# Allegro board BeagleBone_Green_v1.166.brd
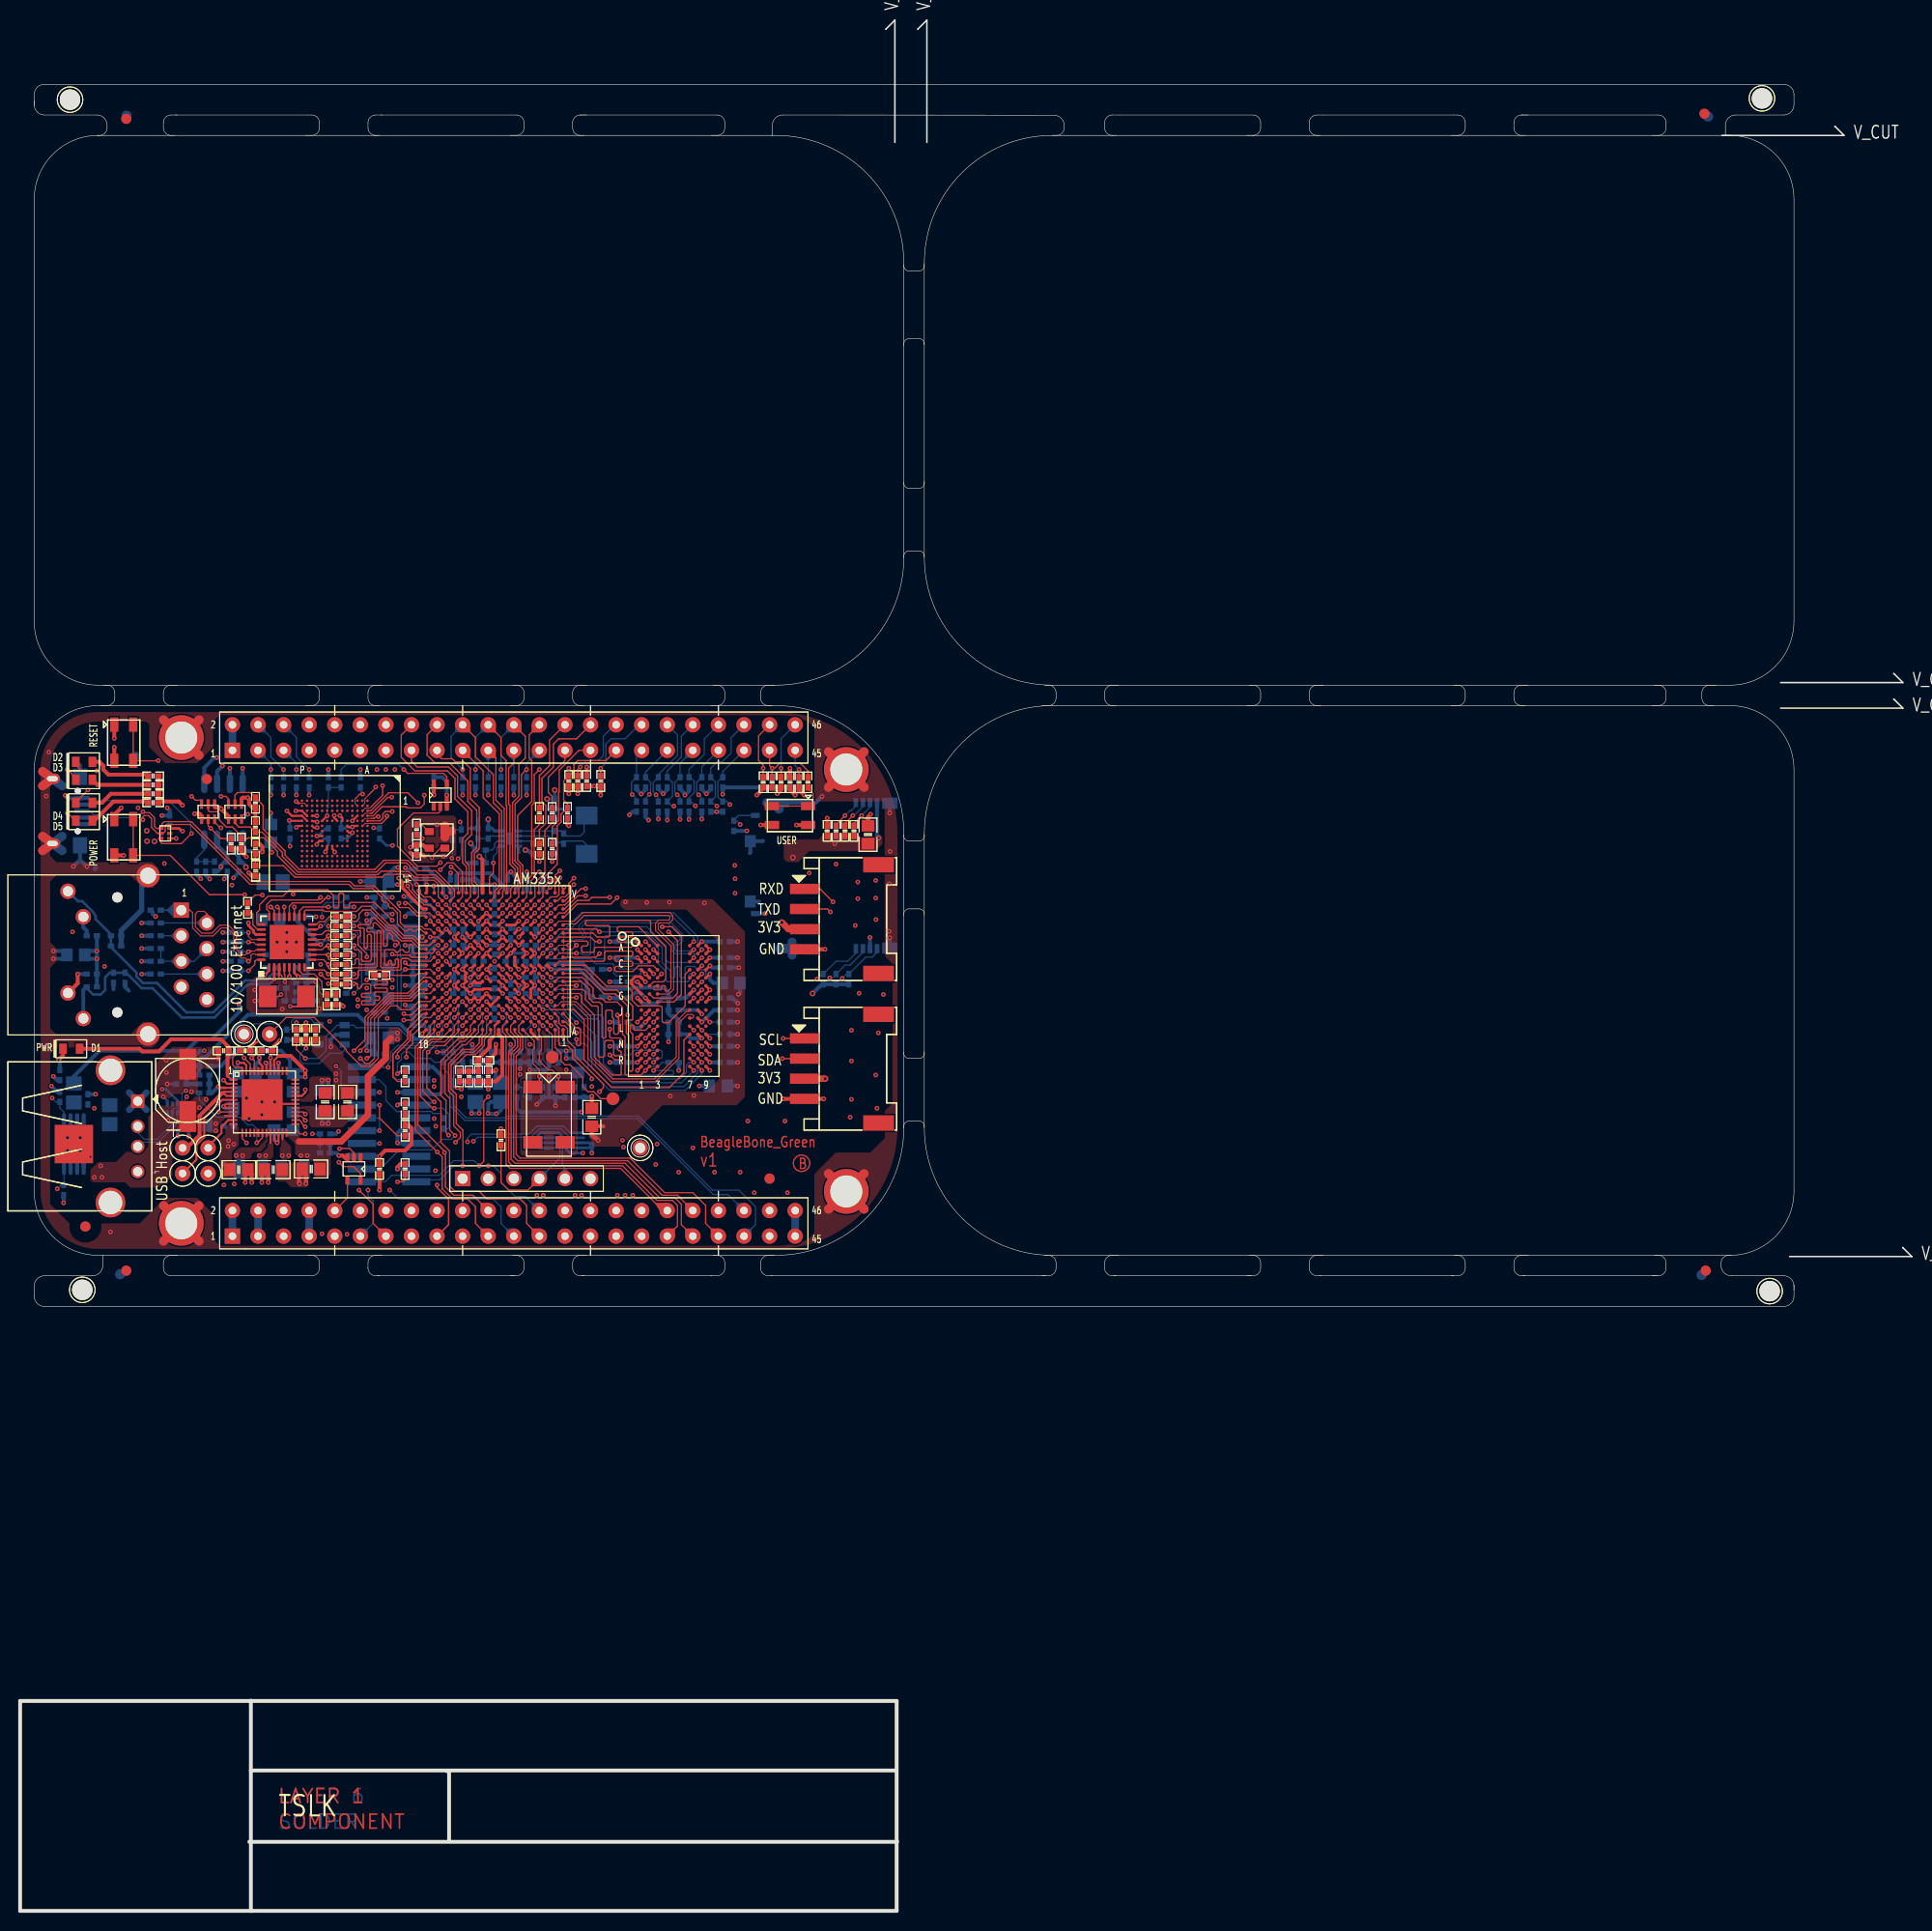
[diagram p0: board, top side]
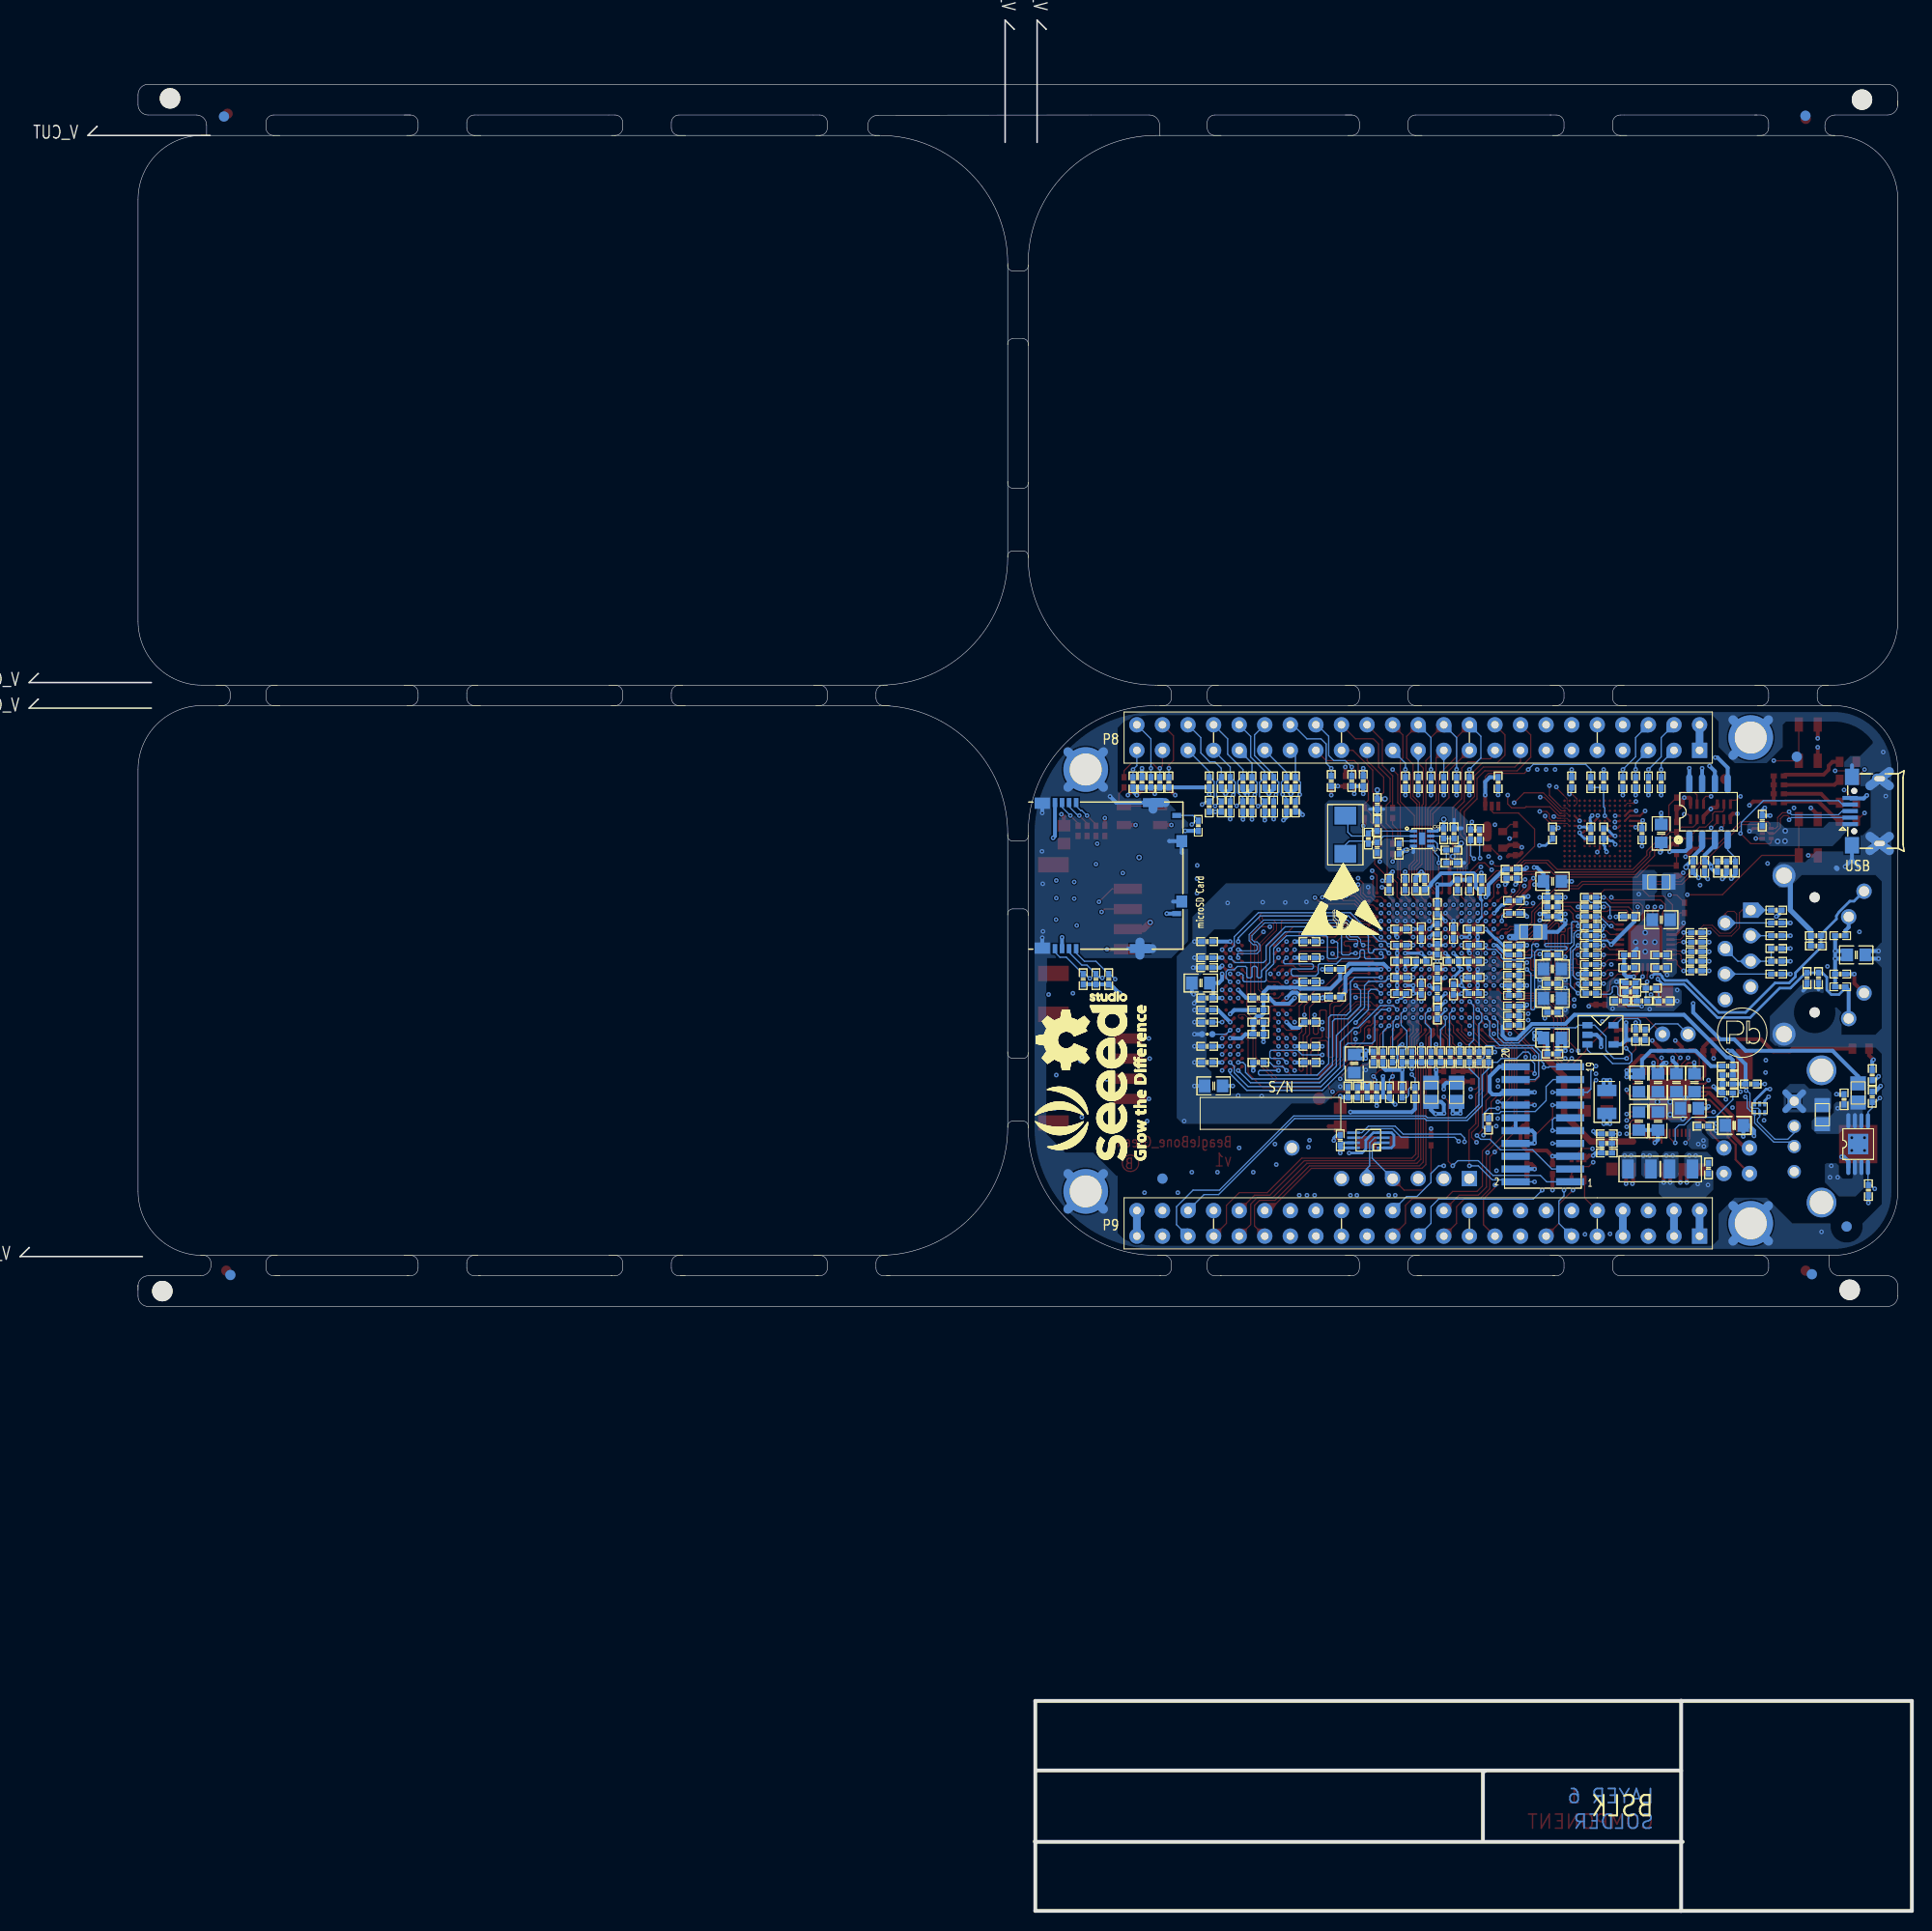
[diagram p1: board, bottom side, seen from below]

Outline 187.86 x 187.83 mm; copper layers: TOP, LYR2_GND, LYR3, LYR4, LYR5_PWR, BOTTOM. Coordinates in mm from the lower left corner of the outline.

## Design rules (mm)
net group RX: nets RXN RXP
net group TX: nets TXN TXP
net group USB0: nets USB0_DM USB0_DP
net group USB1: nets USB1_DM USB1_DP
net group CLK: nets MMC0_CLKO
net group DDR_ADD: nets DDR_A0 DDR_A1 DDR_A2 DDR_A3 DDR_A4 DDR_A5 DDR_A6 DDR_A7 DDR_A8 DDR_A9 DDR_A10 DDR_A11 DDR_A12 DDR_A13 DDR_A14 DDR_BA0 DDR_BA1 DDR_BA2 DDR_CASN DDR_CKE DDR_CLK DDR_CLKN DDR_CSN DDR_ODT DDR_RASN DDR_WEN
net group DDR_DQ0: nets DDR_D0 DDR_D1 DDR_D2 DDR_D3 DDR_D4 DDR_D5 DDR_D6 DDR_D7 DDR_DQM0 DDR_DQS0 DDR_DQSN0
net group DDR_DQ1: nets DDR_D8 DDR_D9 DDR_D10 DDR_D11 DDR_D12 DDR_D13 DDR_D14 DDR_D15 DDR_DQM1 DDR_DQS1 DDR_DQSN1
nets with their own width: min track width 0.203; nets USB1_VBUS

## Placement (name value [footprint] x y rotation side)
C1  10uF,10V  [805]  21.72 73.63 180 top
C2  10uF,10V  [805]  17.63 78.03 0 bottom
C3  0.1uf,6.3V  [402]  22.35 85.45 180 top
C4  10uF,10V  [805]  21.59 82.27 90 bottom
C7  10uF,10V  [805]  25.21 78.46 270 bottom
C8  10uF,10V  [805]  27.11 78.46 270 bottom
C9  10uF,10V  [805]  25.15 73.63 180 top
C10  10uF,10V  [805]  22.1 79.73 180 bottom
C11  10uF,10V  [805]  30.29 80.37 270 top
C12  10uF,10V  [805]  28.89 73.7 0 top
C13  10uF,10V  [805]  25.21 82.27 90 bottom
C14  10uF,10V  [805]  27.11 82.27 90 bottom
C15  10uF,10V  [805]  23.37 82.27 90 bottom
C16  2.2uF,6.3V  [402]  16 82.14 180 bottom
C17  2.2uF,6.3V  [402]  21.72 103.73 270 bottom
C18  2.2uF,6.3V  [402]  20.19 85.45 180 top
C19  470pF,6.3V  [402]  18.41 103.73 270 bottom
C20  0.1uf,6.3V  [402]  20.57 103.73 270 bottom
C21  18pF,50V  [402]  51.88 81.32 90 bottom
C22  18pF,50V  [402]  53.15 81.32 90 bottom
C24  2.2uF,6.3V  [402]  30.29 76.24 0 bottom
C25  18pF,50V  [402]  53.09 107.8 90 bottom
C26  18pF,50V  [402]  53.09 105.64 270 bottom
C28  0.1uf,6.3V  [402]  57.28 93.54 0 bottom
C29  0.1uf,6.3V  [402]  35.69 73.7 270 top
C30  0.1uf,6.3V  [402]  30.29 75.29 0 bottom
C31  0.1uf,6.3V  [402]  44.58 82.91 270 top
C32  0.001uf,50V  [402]  43.62 82.91 270 top
C33  0.1uf,6.3V  [402]  45.53 82.91 270 top
C34  100uF,6.3V  [RD205SMD_250D]  16.64 81.51 90 top
C35  0.1uf,6.3V  [402]  6.73 80.62 90 bottom
C36  0.1uf,6.3V  [402]  14.86 108.31 90 bottom
C37  0.1uf,6.3V  [402]  29.34 87.03 270 top
C38  0.1uf,6.3V  [402]  35.69 99.73 180 bottom
C39  10uF,10V  [805]  35.69 90.65 0 bottom
C40  10uF,10V  [805]  35.69 93.57 0 bottom
C41  0.1uf,6.3V  [402]  43.52 97.54 180 bottom
C42  0.1uf,6.3V  [402]  47.12 97.54 270 bottom
C43  0.1uf,6.3V  [402]  48.72 97.14 90 bottom
C44  0.1uf,6.3V  [402]  39.52 90.94 180 bottom
C45  0.1uf,6.3V  [402]  39.5 94.97 180 bottom
C46  0.1uf,6.3V  [402]  45.52 94.34 0 bottom
C47  0.1uf,6.3V  [402]  47.12 95.54 270 bottom
C48  0.1uf,6.3V  [402]  48.72 94.34 0 bottom
C49  0.1uf,6.3V  [402]  47.12 93.14 90 bottom
C50  0.1uf,6.3V  [402]  48.72 91.54 90 bottom
C51  0.1uf,6.3V  [402]  35.69 94.97 180 bottom
C52  0.1uf,6.3V  [402]  35.69 92.11 180 bottom
C53  0.1uf,6.3V  [402]  35.69 89.26 180 bottom
C54  0.1uf,6.3V  [402]  39.52 91.94 180 bottom
C55  10uF,10V  [805]  32.51 80.37 270 top
C56  0.1uf,6.3V  [402]  47.12 99.54 270 bottom
C57  0.1uf,6.3V  [402]  56.26 112.24 270 top
C58  0.1uf,6.3V  [402]  43.92 101.94 90 bottom
C59  0.1uf,6.3V  [402]  44.89 84.81 270 bottom
C60  0.1uf,6.3V  [402]  43.52 92.74 180 bottom
C61  0.1uf,6.3V  [402]  76.45 112.12 270 top
C62  10uF,10V  [805]  35.69 86.72 0 bottom
C63  0.1uf,6.3V  [402]  45.52 91.54 90 bottom
C64  0.1uf,6.3V  [402]  35.69 85.13 180 bottom
C65  0.1uf,6.3V  [402]  43.52 94.34 180 bottom
C66  0.1uf,6.3V  [402]  43.52 95.94 180 bottom
C67  0.1uf,6.3V  [402]  35.69 100.69 180 bottom
C68  0.1uf,6.3V  [402]  50.32 101.94 270 bottom
C69  0.1uf,6.3V  [402]  39.52 93.94 0 bottom
C70  0.1uf,6.3V  [402]  43.52 91.14 180 bottom
C71  0.1uf,6.3V  [402]  39.75 102.59 180 bottom
C72  0.1uf,6.3V  [402]  47.12 91.14 270 bottom
C73  0.1uf,6.3V  [402]  50.72 97.54 0 bottom
C74  0.1uf,6.3V  [402]  51.92 101.94 270 bottom
C75  0.1uf,6.3V  [402]  54.48 112.24 270 bottom
C76  0.1uf,6.3V  [402]  76.45 112.12 270 bottom
C77  10uF,10V  [805]  35.69 102.27 180 bottom
C78  0.1uf,6.3V  [402]  35.69 98.78 0 bottom
C79  0.1uf,6.3V  [402]  39.52 92.94 180 bottom
C80  0.1uf,6.3V  [402]  42.72 101.94 90 bottom
C81  0.1uf,6.3V  [402]  49.28 101.96 90 bottom
C82  0.1uf,6.3V  [402]  39.52 89.89 180 bottom
C83  0.1uf,6.3V  [402]  39.52 88.94 180 bottom
C84  0.1uf,6.3V  [402]  48.39 101.96 90 bottom
C85  0.1uf,6.3V  [402]  39.52 87.99 180 bottom
C86  0.1uf,6.3V  [402]  39.52 100.37 180 bottom
C87  0.1uf,6.3V  [402]  39.5 95.86 180 bottom
C88  0.1uf,6.3V  [402]  47.12 89.13 270 bottom
C89  1uF,10V  [402]  47.75 84.81 270 bottom
C90  1uF,10V  [402]  45.85 84.81 270 bottom
C91  1uF,10V  [402]  46.8 84.81 270 bottom
C92  0.1uf,6.3V  [402]  49.66 84.81 270 bottom
C93  0.1uf,6.3V  [402]  46.48 82.91 270 top
C94  0.1uf,6.3V  [402]  45.52 97.14 270 bottom
C95  10uF,10V  [805]  55.37 84.18 90 bottom
C96  10uF,10V  [805]  56.77 78.84 90 top
C97  0.1uf,6.3V  [402]  50.72 95.94 180 bottom
C98  0.1uf,6.3V  [402]  50.72 94.34 180 bottom
C99  0.1uf,6.3V  [402]  50.72 92.74 180 bottom
C100  0.1uf,6.3V  [402]  50.72 91.14 180 bottom
C101  0.1uf,6.3V  [402]  53.47 84.81 270 bottom
C102  0.1uf,6.3V  [402]  55.05 81.32 90 bottom
C103  0.1uf,6.3V  [402]  56.01 81.32 90 bottom
C104  1uF,10V  [402]  50.61 84.81 270 bottom
C105  0.1uf,6.3V  [402]  48.7 84.81 270 bottom
C106  1uF,10V  [402]  45.12 101.94 90 bottom
C107  0.1uf,6.3V  [402]  59.82 96.29 180 bottom
C108  0.1uf,6.3V  [402]  59.82 94.69 180 bottom
C109  0.1uf,6.3V  [402]  59.82 92.29 180 bottom
C110  0.1uf,6.3V  [402]  59.82 90.69 180 bottom
C111  0.1uf,6.3V  [402]  59.82 88.29 180 bottom
C112  0.1uf,6.3V  [402]  59.82 85.89 180 bottom
C113  0.1uf,6.3V  [402]  59.82 84.29 180 bottom
C114  0.1uf,6.3V  [402]  69.98 96.29 0 bottom
C115  0.1uf,6.3V  [402]  69.98 94.69 0 bottom
C116  0.1uf,6.3V  [402]  69.98 93.7 0 bottom
C117  0.1uf,6.3V  [402]  69.98 90.69 0 bottom
C118  10uF,10V  [805]  70.61 92.18 180 bottom
C119  0.1uf,6.3V  [402]  69.98 89.49 0 bottom
C120  0.1uf,6.3V  [402]  69.98 85.89 0 bottom
C121  0.1uf,6.3V  [402]  69.98 84.29 0 bottom
C122  10uF,10V  [805]  69.34 81.95 180 bottom
C123  0.001uf,50V  [402]  64.9 89.49 0 bottom
C124  0.1uf,6.3V  [402]  64.9 87.09 180 bottom
C125  2.2uF,6.3V  [402]  33.78 112.12 90 bottom
C126  10uF,10V  [805]  24.89 107.04 90 bottom
C127  0.1uf,6.3V  [402]  26.8 107.04 270 bottom
C128  0.1uf,6.3V  [402]  30.61 107.04 90 bottom
C129  0.1uf,6.3V  [402]  31.88 107.04 270 bottom
C130  0.1uf,6.3V  [402]  35.69 107.04 270 bottom
C131  0.1uf,6.3V  [402]  24.89 93.7 0 bottom
C132  0.1uf,6.3V  [402]  24.89 94.97 0 bottom
C133  10uF,10V  [805]  24.89 98.46 180 bottom
C134  1uF,10V  [402]  28.07 93.7 180 bottom
C135  0.1uf,6.3V  [402]  28.07 98.78 0 bottom
C136  470pF,6.3V  [0402]  28.07 94.97 180 bottom
C137  33pF,4 EMI  [402]  13.46 99.42 180 bottom
C138  33pF,4 EMI  [402]  13.46 98.15 180 bottom
C139  33pF,4 EMI  [402]  13.46 96.88 180 bottom
C140  33pF,4 EMI  [402]  13.46 93.07 180 bottom
C141  0.022uF,10V  [402]  13.46 95.61 180 bottom
C142  30pF,50V  [402]  24.64 90.4 180 bottom
C143  30pF,50V  [402]  28.96 90.4 0 bottom
C152  0.1uf,6.3V  [402]  27.43 87.03 90 bottom
C153  10uF,10V  [805]  84.2 106.91 90 top
C154  0.1uf,6.3V  [402]  80.14 107.29 90 top
C155  0.1uf,6.3V  [402]  56.77 76.56 270 bottom
C158  0.1uf,6.3V  [402]  41.08 112.12 90 bottom
C159  0.1uf,6.3V  [402]  39.37 105.38 270 top
C161  33pF,4 EMI  [402]  27.94 92.18 0 bottom
C162  33pF,4 EMI  [402]  30.48 90.53 90 top
C163  100pF,4 EMI  [402]  9.53 96.88 0 bottom
C164  100pF,4 EMI  [402]  10.41 92.68 270 bottom
C165  100nF,4 EMI  [402]  9.53 95.86 0 bottom
C166  100nF,4 EMI  [402]  9.27 92.68 270 bottom
D1  LTST-C191TBKT  [LED_0603]  5.08 85.65 0 top
D2  LTST-C191TBKT  [LED_0603]  6.35 114.15 0 top
D3  LTST-C191TBKT  [LED_0603]  6.35 112.37 0 top
D4  LTST-C191TBKT  [LED_0603]  6.35 110.08 0 top
D5  LTST-C191TBKT  [LED_0603]  6.35 108.31 0 top
FB1  150OHM800mA  [SM-7351-IND-0805]  37.85 97.26 0 bottom
FB2  150OHM800mA  [SM-7351-IND-0805]  47.75 81.32 270 bottom
FB3  150OHM800mA  [SM-7351-IND-0805]  45.21 81.32 270 bottom
FB4  150OHM800mA  [SM-7351-IND-0805]  25.12 102.21 180 bottom
FB7  150OHM800mA  [SM-7351-IND-0805]  8.89 79.1 90 bottom
FB8  0.1R,0805  [SM-7351-IND-0805]  5.33 81.25 270 bottom
J1  HEADER 6  [SIP6]  43.94 72.75 90 top
J4  GroveHDR  [4P-SMD-2_0-90D]  77.85 83.67 270 top
J5  GroveHDR  [4P-SMD-2_0-90D]  77.85 98.53 270 top
L1  LQM2HPN2R2MG0L  [2520]  22.92 73.7 180 bottom
L2  LQM2HPN2R2MG0L  [2520]  27.05 73.7 0 bottom
L3  LQM2HPN2R2MG0L  [2520]  30.29 80.37 270 bottom
MTG1  MHOLE  [MTGH200C125D_PL]  16 68.3 90 top
MTG2  MHOLE  [MTGH200C125D_PL]  82.04 71.48 90 top
MTG3  MHOLE  [MTGH200C125D_PL]  16 116.56 90 top
MTG4  MHOLE  [MTGH200C125D_PL]  82.04 113.39 90 top
NOREF  -  []  82.04 71.48 0 top
NOREF#2  -  []  87.76 93.07 0 top
NOREF#3  -  []  87.76 77.83 0 top
NOREF#4  -  [unnamed#2]  173.74 61.57 0 top
NOREF#5  -  []  16 116.56 0 top
NOREF#6  -  [unnamed#3]  74.42 72.75 270 top
NOREF#7  -  []  87.76 104.81 0 top
NOREF#8  -  [unnamed#3]  167.26 178.54 270 top
NOREF#9  -  []  7.75 119.74 0 top
NOREF#10  -  []  16 68.3 0 top
NOREF#11  -  [unnamed#3]  167.39 63.6 270 top
NOREF#12  -  [unnamed#3]  10.54 63.6 270 top
NOREF#13  -  []  87.12 93.7 0 top
NOREF#14  -  []  16 68.3 0 top
NOREF#15  -  [unnamed#3]  6.48 67.98 270 top
NOREF#16  -  []  1.4 65.13 0 top
NOREF#17  -  []  83.31 117.2 0 top
NOREF#18  -  []  82.04 113.39 0 top
NOREF#19  -  [unnamed#3]  10.54 178.03 270 top
NOREF#20  -  []  -366.77 -191.34 0 top
NOREF#21  -  []  82.04 71.48 0 top
NOREF#22  -  [unnamed#2]  172.97 180.06 180 top
NOREF#23  -  []  1.4 65.13 0 top
NOREF#24  -  []  87.12 104.18 0 top
NOREF#25  -  [unnamed#3]  18.54 112.43 270 top
NOREF#26  -  [unnamed#2]  6.17 61.7 0 top
NOREF#27  -  [unnamed#2]  4.95 179.93 180 top
NOREF#28  -  []  1.4 53.16 0 top
NOREF#29  -  []  -10.57 65.13 90 top
NOREF#30  -  []  -366.9 -191.41 0 top
NOREF#31  -  []  87.12 93.7 0 top
NOREF#32  -  [unnamed#3]  166.98 63.17 270 bottom
NOREF#33  -  [unnamed#3]  11.43 114.66 270 bottom
NOREF#34  -  [unnamed#3]  167.61 178.26 90 bottom
NOREF#35  -  [unnamed#3]  9.93 63.25 270 bottom
NOREF#36  -  []  3.3 118.47 180 bottom
NOREF#37  -  [unnamed#3]  10.57 178.33 90 bottom
NOREF#38  -  [unnamed#3]  74.42 72.75 270 bottom
NOREF#39  -  []  85.22 79.1 90 bottom
NOREF#40  -  [unnamed#3]  6.48 67.98 270 bottom
P2  CTI JTAG,DNI  [HEADER10X2_SMD]  36.64 78.14 90 bottom
P3  DIP USB A TYPE FMAL  [USB-003A-4P-90D]  8.97 76.94 270 top
P4  SMD Micro USB-B-without POST-W/P  [5P-USB-B]  6.38 109.26 90 bottom
P5  LPJ0011BBNL  [RJ45-7499010211A]  16 99.42 270 top
P8  FEMALE HEADER 2x23  [HEADER23X2]  21.08 115.29 0 top
P9  FEMALE HEADER 2x23  [HEADER23X2]  21.08 67.03 0 top
P10  SCHA5B0200  [SD-MICRO-SCHA5B0300]  82.99 102.84 270 bottom
Q1  DMC56404  [SMINI6-F3-B]  21.34 109.19 180 top
Q2  DMC56404  [SMINI6-F3-B]  18.67 109.19 180 top
R1  100K,1%  [402]  24.51 85.45 180 top
R3  1.5K,1%  [402]  27.43 87.03 270 top
R4  1.5K,1%  [402]  28.38 87.03 270 top
R5  0,1%  [402]  18.29 82.14 180 bottom
R6  0,1%  [402]  20.19 73.76 270 bottom
R7  0,1%  [402]  18.29 81.25 180 bottom
R8  0,1%  [402]  18.29 83.03 180 bottom
R9  0,1%,DNI  [402]  18.29 83.92 0 bottom
R10  470K,1%  [402]  17.53 103.73 270 bottom
R11  280K,1%  [402]  19.3 103.73 90 bottom
R12  4.75K,5%  [402]  3.94 83.03 90 bottom
R14  10K,1%  [402]  30.29 77.19 180 bottom
R17  1M,1%  [402]  53.98 106.53 270 bottom
R18  33  [0402]  42.04 78.21 90 bottom
R19  0,1%  [402]  42.99 84.81 270 bottom
R20  0,1%  [402]  43.94 84.81 90 bottom
R22  49.9,1%  [402]  57.28 90.78 180 bottom
R23  4.75K,1%  [402]  38.23 77.51 270 top
R24  4.75K,1%  [402]  38.23 79.73 90 top
R25  4.75K,1%  [402]  38.23 73.7 90 top
R26  4.75K,1%  [402]  51.56 84.81 90 bottom
R27  0,1%  [402]  46.01 84.49 180 top
R28  33  [0402]  35.69 92.94 180 top
R29  0,1%  [402]  53.09 109.96 270 bottom
R30  0,1%  [402]  54.1 81.32 270 bottom
R45  22  [0402]  51.56 109.07 90 top
R46  0  [0402]  52.83 109.07 90 top
R47  0  [0402]  52.83 105.51 90 top
R48  0  [0402]  51.56 105.51 90 top
R49  0,1%  [402]  39.5 99.1 0 bottom
R50  0,1%  [402]  38.23 82.91 270 top
R51  0,1%  [402]  42.04 84.81 90 bottom
R52  10K,1%  [402]  3.94 80.87 270 bottom
R53  10K,1%  [402]  4.32 71.6 270 bottom
R54  10K,1%  [402]  52.51 84.81 90 bottom
R55  100K,1%,DNI  [402]  55.63 112.24 90 bottom
R56  100K,1%  [402]  54.48 112.24 90 top
R57  100K,1%,DNI  [402]  61.21 112.12 90 bottom
R58  100K,1%,DNI  [402]  62.1 112.12 90 bottom
R59  100K,1%,DNI  [402]  57.66 112.24 90 bottom
R60  100K,1%,DNI  [402]  63.37 112.12 90 bottom
R61  100K,1%,DNI  [402]  64.26 112.12 90 bottom
R62  100K,1%,DNI  [402]  65.53 112.12 90 bottom
R63  100K,1%,DNI  [402]  66.42 112.12 90 bottom
R64  100K,1%,DNI  [402]  67.69 112.12 90 bottom
R65  100K,1%  [402]  68.58 112.12 90 bottom
R66  100K,1%  [402]  69.77 112.12 90 bottom
R67  100K,1%  [402]  73.79 112.12 90 bottom
R68  100K,1%  [402]  74.68 112.12 90 bottom
R69  100K,1%,DNI  [402]  75.57 112.12 90 bottom
R70  100K,1%,DNI  [402]  77.34 112.12 90 bottom
R71  4.75K,5%  [402]  13.21 110.08 180 top
R72  4.75K,5%  [402]  13.21 112.75 180 top
R73  4.75K,5%  [402]  13.21 111.86 180 top
R74  4.75K,5%  [402]  13.21 110.97 180 top
R75  100,1%  [402]  78.23 112.12 270 top
R76  100K,1%  [402]  23.37 107.67 90 top
R77  100K,1%  [402]  23.37 110.08 270 top
R78  100K,1%  [402]  20.95 106.02 270 top
R79  100K,1%  [402]  21.97 106.02 270 top
R80  100K,1%  [402]  55.37 112.24 270 top
R81  100K,1%,DNI  [402]  54.36 109.07 270 top
R82  100K,1%  [402]  61.21 109.7 270 bottom
R83  100K,1%  [402]  62.1 109.7 270 bottom
R84  100K,1%  [402]  57.66 112.24 270 top
R85  100K,1%  [402]  63.37 109.7 270 bottom
R86  100K,1%  [402]  64.26 109.7 270 bottom
R87  100K,1%  [402]  65.53 109.7 270 bottom
R88  100K,1%  [402]  66.42 109.7 270 bottom
R89  100K,1%  [402]  67.69 109.7 270 bottom
R90  100K,1%,DNI  [402]  68.58 109.7 270 bottom
R91  100K,1%,DNI  [402]  69.77 109.7 270 bottom
R92  100K,1%,DNI  [402]  73.79 112.12 270 top
R93  100K,1%,DNI  [402]  74.68 112.12 270 top
R94  100K,1%  [402]  75.57 112.12 270 top
R95  100K,1%  [402]  77.34 112.12 270 top
R96  10K,1%  [402]  69.98 88.29 180 bottom
R97  1.5K,1%  [402]  64.9 84.29 180 bottom
R98  10K,1%  [402]  64.9 90.69 180 bottom
R99  240  [SM-7351-RES-0402]  69.98 87.09 180 bottom
R100  10K,1%  [402]  64.9 88.29 180 bottom
R101  10K,1%  [402]  50.29 112.12 90 bottom
R102  10K,1%  [402]  47.75 112.12 90 bottom
R103  10K,1%  [402]  27.43 112.12 90 bottom
R104  10K,1%  [402]  28.7 112.12 90 bottom
R105  10K,1%  [402]  49.02 112.12 90 bottom
R106  10K,1%  [402]  45.21 112.12 90 bottom
R107  10K,1%  [402]  24.89 112.12 90 bottom
R108  10K,1%  [402]  26.16 112.12 90 bottom
R109  10K,1%  [402]  43.94 112.12 90 bottom
R110  10K,1%  [402]  46.48 112.12 90 bottom
R111  10K,1%  [402]  30.61 112.12 270 bottom
R112  1.5K,1%  [402]  31.88 95.92 0 bottom
R113  1.5K,1%  [402]  31.88 98.78 0 bottom
R114  1.5K,1%  [402]  31.88 94.97 0 bottom
R115  10K,1%  [402]  31.88 96.88 0 bottom
R116  10K,1%  [402]  31.88 93.07 0 bottom
R117  10K,1%  [402]  31.88 94.02 0 bottom
R118  10K,1%  [402]  31.37 90.53 270 top
R119  1.5K,1%  [402]  31.88 98.78 180 top
R120  49.9,1%  [402]  21.4 94.34 180 bottom
R121  49.9,1%  [402]  21.4 95.29 180 bottom
R122  49.9,1%  [402]  21.4 96.24 180 bottom
R123  49.9,1%  [402]  21.4 97.19 180 bottom
R124  10,1%,DNI  [402]  31.88 92.05 180 top
R125  100,1%  [402]  31.88 93.07 180 top
R126  100,1%  [402]  31.88 94.02 180 top
R127  100,1%  [402]  31.88 94.97 180 top
R128  100,1%  [402]  31.88 95.92 180 top
R129  100,1%  [402]  22.58 99.64 270 top
R130  470,5%  [402]  7.11 93.07 180 bottom
R131  100,1%  [402]  31.88 92.11 180 bottom
R132  470,5%  [402]  7.11 96.88 180 bottom
R133  100,1%  [402]  31.88 96.88 180 top
R134  100,1%  [402]  31.88 100.69 180 bottom
R135  10K,1%  [402]  7.11 91.8 0 bottom
R136  0.1R,0805  [805]  5.52 94.97 180 bottom
R137  0,1%  [402]  13.46 94.34 180 bottom
R138  100,1%  [402]  31.88 97.83 180 bottom
R139  100,1%  [402]  31.88 97.83 180 top
R140  0,1%,DNI  [402]  31.88 91.16 180 bottom
R141  1M,1%,DNI  [402]  26.8 90.4 0 bottom
R142  0,1%  [402]  27.94 91.29 0 bottom
R143  10,1%  [402]  25.91 91.67 180 bottom
R144  12.1K,1%  [402]  21.4 93.38 180 bottom
R145  10K,1%  [402]  31.88 99.73 0 bottom
R150  10K,1%  [402]  81.03 107.29 90 top
R151  10K,1%  [402]  82.8 107.29 90 top
R152  10K,1%  [402]  82.3 92.56 90 bottom
R153  10K,1%  [402]  81.03 92.56 90 bottom
R154  10K,1%  [402]  79.76 92.56 90 bottom
R155  10K,1%  [402]  81.92 107.29 90 top
R156  10K,1%  [402]  26.48 87.03 90 bottom
R157  10K,1%  [402]  70.87 107.8 270 bottom
R159  0,1%  [402]  39.75 103.48 0 bottom
R160  0,1%  [402]  43.81 106.91 90 bottom
R161  0,1%  [402]  42.93 106.91 90 bottom
R162  0,1%  [402]  31.88 112.12 270 bottom
R163  4.75K,1%  [402]  49.34 81.32 90 bottom
R164  4.75K,1%  [402]  50.61 81.32 90 bottom
R165  100K,1%  [402]  47.75 76.56 90 top
R167  33  [0402]  39.37 107.42 270 top
R168  0R,1%  [402]  20.7 77.95 180 bottom
R169  0,1% DNP  [402]  23.37 105.51 90 top
R170  0,1% DNP  [402]  23.39 103.33 270 top
R171  4.75K,5%  [402]  50.93 105.51 90 bottom
R172  4.75K,5%  [402]  45.72 105.38 0 bottom
R173  4.75K,5%  [402]  45.47 107.04 90 bottom
R174  4.75K,5%,DNP  [402]  45.72 104.11 180 bottom
R175  4.75K,5%.DNP  [402]  46.48 107.04 270 bottom
S1  SMD Button Top  [SW_4P]  10.29 116.05 270 top
S2  SMD Button Top  [SW_4P]  76.45 108.81 180 top
S3  SMD Button Top  [SW_4P]  10.29 106.65 270 top
TP1  TESTPT1  [TP1-8040]  61.57 75.79 0 top
TP2  TESTPT1  [TP60C_SMD]  58.86 80.68 0 top
TP3  TESTPT1  [TP60C_SMD]  52.83 84.81 0 top
TP4  TESTPT1  [TP1-8040]  22.22 87.1 0 top
TP5  TESTPT1  [TP60C33D]  16.13 75.79 0 top
TP6  TESTPT1  [TP60C33D]  16.13 73.25 0 top
TP7  TESTPT1  [TP60C33D]  18.67 75.79 0 top
TP8  TESTPT1  [TP60C33D]  18.67 73.25 0 top
TP9  TESTPT1  [TP60C33D]  24.76 87.1 0 top
U2  TPS65217C  [U_48_RSL]  24.26 80.37 0 top
U3  SN74LVC1G06DCK  [DCK5_2P15X1P4]  41.72 110.85 0 top
U4  TL5209  [SO8-25X75]  20.19 109.19 180 bottom
U5  AM3358BZCZ100  [AM33XX_15X15]  47.12 94.34 180 top
U7  24LC32A  [SOT23-5]  30.92 87.03 270 bottom
U8  TPS2051 (DGN)  [DGN-16X60]  5.33 76.17 180 bottom
U9  TPD4S012  [U_6_DRY]  15.11 79.73 180 bottom
U10  TPD4S012  [U_6_DRY]  14.41 107.04 270 top
U12  MT41K256M16HA -125:E  [BGA96_T9_P8_9X14]  64.9 89.89 0 top
U13  MEM_MNAND_4GB  [BGA153_P14_P5_11P5X13]  31.24 107.04 270 top
U14  LAN8710A  [QFN32_5X5MM_EP3P3MM]  26.48 96.24 0 top
U15  SN74LVC2G241  [U_8_DCU]  53.98 76.56 90 bottom
U16  SN74LVC1G07DCK  [DCK5_2P15X1P4]  33.15 73.71 180 top
U17  SSDCI3128AF  [TDFN8_P5_2P0]  48.64 106.53 270 bottom
Y1  32.768KHz MC-306  [XTAL4_126-216SMD]  52.51 79.1 270 top
Y2  24MHz  [XTAL150SMD_125X196]  56.26 106.91 90 bottom
Y3  25.000MHz  [XTAL150SMD_125X196]  26.48 90.84 180 top
Y4  24.576MHZ  [OSC4_61X65LS_79X98SMD]  41.4 106.4 90 top

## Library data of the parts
C1 C2 C4 C7-C15 C39 C40 C55 C62 C77 C95 C96 C118 C122 C126 C133 C153 = CAP_10uF_Y5V_10V_10%_0805
C3 C20 C28-C31 C33 C35-C38 C41-C54 C56-C61 C63-C76 C78-C88 C92-C94 C97-C103 C105 C107-C117 C119-C121 C124 C127-C132 C135 C152 C154 C155 C158 C159 = CAP_0.1uF_X5R_6.3V_20% 0201
C16-C18 C125 = CAP_2.2uF_X5R_6.3V_10%_0402
C19 = CAP_470PF_X7R_25V_10%_0402
C21 C22 C25 C26 = CAP_18PF_COG_50V_5%_0402
C24 C89-C91 C104 C106 C134 = CAP_1.0UF_X5R_10V_10%_0402
C32 C123 = CAP_0.001_X7R_50V_5%_0402
C34 = CAP_100UF_TANT_6.3V_3528-21
C136 = 470pF/5%/50V/C0G/0603_0
C137-C140 C161-C166 = CAP_0402_100pF_COG_50V
C141 = CAP_0402_0.1uf_X5R_10V
C142 C143 = CAP_30PF_COG_50V_5%_0402
D1-D5 = LED_LTST-C150GKT_0
FB1-FB4 FB7 FB8 = FER_180_200_0
J1 = HEADER 6: User Part Number: ***
J4 J5 = HEADER 4
L1-L3 = IND_2.2uH_2.6A_10%_SMD
MTG1-MTG4 = MHOLE
P2 = HDR_10x2_CJTAG_0
P3 = CONN_54819-0578_2
P4 = MINI-USB-AB-SOCKET
P5 = CONN_RJ45_MAG_WE_0
P8 P9 = HDR_46_F_2_0.1_0.1
P10 = microSD_CONN_8: User Part Number: X; Tolerance: X
Q1 Q2 = RN1907
R1 R55-R70 R75-R95 R165 = RES_100K_1/16W_1%_0402
R3 R4 R119 R168 = RES_1.5K_1/16W_5%_0402
R5-R9 R23-R26 R50 R51 R112-R118 R159-R164 R169 R170 = RES_4.75K_1/16W_1%_0402
R10 R12 R71-R74 R130 R132 R171-R175 = RES_470_1/10W_5%_0402
R11 = RES_470_1/10W_5%_0402: signal model: 33OHMRESISTOR1_16W5_0402_SM_735_33
R14 = RES_10K_1/16W_1%_0402: signal model: 33OHMRESISTOR1_16W5_0402_SM_735_33
R17 = RES_1M_1/16W_1%_0402: signal model: 33OHMRESISTOR1_16W5_0402_SM_735_33
R18 R47 = RES_33_0402: signal model: 33OHMRESISTOR1_16W5_0402_SM_735_33
R19 R27 R29 R30 R140 R142 R156 = RES_0_1/16W_1%_0402
R20 = RES_0_1/16W_1%_0402: signal model: 33OHMRESISTOR1_16W5_0402_SM_735_33
R22 R120-R123 = RES_4.7K_0402
R28 R45 R46 R48 R167 = RES_33_0402
R49 = RES_100K_1/16W_1%_0402: signal model: 33OHMRESISTOR1_16W5_0402_SM_735_33
R52-R54 R96-R98 R100-R111 R135 R137 R143 R145 R150-R155 R157 = RES_10K_1/16W_1%_0402
R99 = Res
R124-R126 R129 R134 R138 = 100-1/10W-1%-0603_4
R127 R128 R131 R133 R139 = RES_100_1/10W_5%_0402
R136 = RES_0.1_0805
R141 = RES_1M_1/16W_1%_0402
R144 = RES_12.1K_1/16W_1%_0402
S1 S3 = SW_KT11P2JM_2
S2 = SW_KT11P2JM_1
TP1-TP9 = TESTPT1
U2 = PWR_TPS65217_2
U3 = IC_SN74LVC1G06DCK_0
U4 = PWR_TLV70233DBV_0: Tolerance: X; User Part Number: X
U5 = IC_AM335X_ZCZ
U7 = MEM_24LC32_SOT23-5
U8 = TPS2061_1: User Part Number: X; Tolerance: X
U9 U10 = PROT_TPD4S012
U12 = MT47H256M8_7
U13 = MEM_MNAND_2GB
U14 = LAN8710 QFN32_1
U15 = IC_SN74LVC2G241_1
U16 = IC_SN74LVC1G07DCK
U17 = SSDCI3128AF
Y1 = CRYS_32_768KHz_SMD32_1
Y2 = CRYS_24MHz_SCC_0
Y3 = Suntsu ITEMP 25MHz _0.005% 20pf
Y4 = OSC_12MHz_1.3V: Tolerance: TOL*; User Part Number: P/N*

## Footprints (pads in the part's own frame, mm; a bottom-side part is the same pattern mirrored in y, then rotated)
4P-SMD-2_0-90D
  rect 1.524x3.048 smd: (-5.4,7.4) (5.4,7.4)
  rect 1.016x2.794 smd: 1(-3,0) 2(-1,0) 3(1,0) 4(3,0)
5P-USB-B
  round 0.61 hole 0.61 unplated: (-2,-0.65) (2,-0.65)
  rect 0.406x1.524 smd: 1(-1.3,-0.25) 2(-0.65,-0.25) 3(0,-0.25) 4(0.65,-0.25) 5(1.3,-0.25)
  rect 1.626x1.397 smd: 6(3.4,-0.427) 7(-3.4,-0.427)
  oval 1.016x1.524 hole 0.508x1.067: 8(-3.22,-3.175) 9(3.22,-3.175)
402
  rect 0.635x0.508 smd: 1(-0.508,0) 2(0.508,0)
0402
  rect 0.635x0.508 smd: 1(-0.508,0) 2(0.508,0)
805
  rect 1.143x1.27 smd: 1(-0.889,0) 2(0.889,0)
2520
  rect 1.143x1.905 smd: 1(-1.143,0) 2(1.143,0)
AM33XX_15X15
  round 0.356 smd: A1(-6.8,6.8) A2(-6,6.8) A3(-5.2,6.8) A4(-4.4,6.8) A5(-3.6,6.8) A6(-2.8,6.8) A7(-2,6.8) A8(-1.2,6.8) A9(-0.4,6.8) A10(0.4,6.8) A11(1.2,6.8) A12(2,6.8) A13(2.8,6.8) A14(3.6,6.8) A15(4.4,6.8) A16(5.2,6.8) A17(6,6.8) A18(6.8,6.8) B1(-6.8,6) B2(-6,6) B3(-5.2,6) B4(-4.4,6) B5(-3.6,6) B6(-2.8,6) B7(-2,6) B8(-1.2,6) B9(-0.4,6) B10(0.4,6) B11(1.2,6) B12(2,6) B13(2.8,6) B14(3.6,6) B15(4.4,6) B16(5.2,6) B17(6,6) B18(6.8,6) C1(-6.8,5.2) C2(-6,5.2) C3(-5.2,5.2) C4(-4.4,5.2) C5(-3.6,5.2) C6(-2.8,5.2) C7(-2,5.2) C8(-1.2,5.2) C9(-0.4,5.2) C10(0.4,5.2) C11(1.2,5.2) C12(2,5.2) C13(2.8,5.2) C14(3.6,5.2) C15(4.4,5.2) C16(5.2,5.2) C17(6,5.2) C18(6.8,5.2) D1(-6.8,4.4) D2(-6,4.4) D3(-5.2,4.4) D4(-4.4,4.4) D5(-3.6,4.4) D6(-2.8,4.4) D7(-2,4.4) D8(-1.2,4.4) D9(-0.4,4.4) D10(0.4,4.4) D11(1.2,4.4) D12(2,4.4) D13(2.8,4.4) D14(3.6,4.4) D15(4.4,4.4) D16(5.2,4.4) D17(6,4.4) D18(6.8,4.4) E1(-6.8,3.6) E2(-6,3.6) E3(-5.2,3.6) E4(-4.4,3.6) E5(-3.6,3.6) E6(-2.8,3.6) E7(-2,3.6) E8(-1.2,3.6) E9(-0.4,3.6) E10(0.4,3.6) E11(1.2,3.6) E12(2,3.6) E13(2.8,3.6) E14(3.6,3.6) E15(4.4,3.6) E16(5.2,3.6) E17(6,3.6) E18(6.8,3.6) F1(-6.8,2.8) F2(-6,2.8) F3(-5.2,2.8) F4(-4.4,2.8) F5(-3.6,2.8) F6(-2.8,2.8) F7(-2,2.8) F8(-1.2,2.8) F9(-0.4,2.8) F10(0.4,2.8) F11(1.2,2.8) F12(2,2.8) F13(2.8,2.8) F14(3.6,2.8) F15(4.4,2.8) F16(5.2,2.8) F17(6,2.8) F18(6.8,2.8) G1(-6.8,2) G2(-6,2) G3(-5.2,2) G4(-4.4,2) G5(-3.6,2) G6(-2.8,2) G7(-2,2) G8(-1.2,2) G9(-0.4,2) G10(0.4,2) G11(1.2,2) G12(2,2) G13(2.8,2) G14(3.6,2) G15(4.4,2) G16(5.2,2) G17(6,2) G18(6.8,2) H1(-6.8,1.2) H2(-6,1.2) H3(-5.2,1.2) H4(-4.4,1.2) H5(-3.6,1.2) H6(-2.8,1.2) H7(-2,1.2) H8(-1.2,1.2) H9(-0.4,1.2) H10(0.4,1.2) H11(1.2,1.2) H12(2,1.2) H13(2.8,1.2) H14(3.6,1.2) H15(4.4,1.2) H16(5.2,1.2) H17(6,1.2) H18(6.8,1.2) J1(-6.8,0.4) J2(-6,0.4) J3(-5.2,0.4) J4(-4.4,0.4) J5(-3.6,0.4) J6(-2.8,0.4) J7(-2,0.4) J8(-1.2,0.4) J9(-0.4,0.4) J10(0.4,0.4) J11(1.2,0.4) J12(2,0.4) J13(2.8,0.4) J14(3.6,0.4) J15(4.4,0.4) J16(5.2,0.4) J17(6,0.4) J18(6.8,0.4) K1(-6.8,-0.4) K2(-6,-0.4) K3(-5.2,-0.4) K4(-4.4,-0.4) K5(-3.6,-0.4) K6(-2.8,-0.4) K7(-2,-0.4) K8(-1.2,-0.4) K9(-0.4,-0.4) K10(0.4,-0.4) K11(1.2,-0.4) K12(2,-0.4) K13(2.8,-0.4) K14(3.6,-0.4) K15(4.4,-0.4) K16(5.2,-0.4) K17(6,-0.4) K18(6.8,-0.4) L1(-6.8,-1.2) L2(-6,-1.2) L3(-5.2,-1.2) L4(-4.4,-1.2) L5(-3.6,-1.2) L6(-2.8,-1.2) L7(-2,-1.2) L8(-1.2,-1.2) L9(-0.4,-1.2) L10(0.4,-1.2) L11(1.2,-1.2) L12(2,-1.2) L13(2.8,-1.2) L14(3.6,-1.2) L15(4.4,-1.2) L16(5.2,-1.2) L17(6,-1.2) L18(6.8,-1.2) M1(-6.8,-2) M2(-6,-2) M3(-5.2,-2) M4(-4.4,-2) M5(-3.6,-2) M6(-2.8,-2) M7(-2,-2) M8(-1.2,-2) M9(-0.4,-2) M10(0.4,-2) M11(1.2,-2) M12(2,-2) M13(2.8,-2) M14(3.6,-2) M15(4.4,-2) M16(5.2,-2) M17(6,-2) M18(6.8,-2) N1(-6.8,-2.8) N2(-6,-2.8) N3(-5.2,-2.8) N4(-4.4,-2.8) N5(-3.6,-2.8) N6(-2.8,-2.8) N7(-2,-2.8) N8(-1.2,-2.8) N9(-0.4,-2.8) N10(0.4,-2.8) N11(1.2,-2.8) N12(2,-2.8) N13(2.8,-2.8) N14(3.6,-2.8) N15(4.4,-2.8) N16(5.2,-2.8) N17(6,-2.8) N18(6.8,-2.8) P1(-6.8,-3.6) P2(-6,-3.6) P3(-5.2,-3.6) P4(-4.4,-3.6) P5(-3.6,-3.6) P6(-2.8,-3.6) P7(-2,-3.6) P8(-1.2,-3.6) P9(-0.4,-3.6) P10(0.4,-3.6) P11(1.2,-3.6) P12(2,-3.6) P13(2.8,-3.6) P14(3.6,-3.6) P15(4.4,-3.6) P16(5.2,-3.6) P17(6,-3.6) P18(6.8,-3.6) R1(-6.8,-4.4) R2(-6,-4.4) R3(-5.2,-4.4) R4(-4.4,-4.4) R5(-3.6,-4.4) R6(-2.8,-4.4) R7(-2,-4.4) R8(-1.2,-4.4) R9(-0.4,-4.4) R10(0.4,-4.4) R11(1.2,-4.4) R12(2,-4.4) R13(2.8,-4.4) R14(3.6,-4.4) R15(4.4,-4.4) R16(5.2,-4.4) R17(6,-4.4) R18(6.8,-4.4) T1(-6.8,-5.2) T2(-6,-5.2) T3(-5.2,-5.2) T4(-4.4,-5.2) T5(-3.6,-5.2) T6(-2.8,-5.2) T7(-2,-5.2) T8(-1.2,-5.2) T9(-0.4,-5.2) T10(0.4,-5.2) T11(1.2,-5.2) T12(2,-5.2) T13(2.8,-5.2) T14(3.6,-5.2) T15(4.4,-5.2) T16(5.2,-5.2) T17(6,-5.2) T18(6.8,-5.2) U1(-6.8,-6) U2(-6,-6) U3(-5.2,-6) U4(-4.4,-6) U5(-3.6,-6) U6(-2.8,-6) U7(-2,-6) U8(-1.2,-6) U9(-0.4,-6) U10(0.4,-6) U11(1.2,-6) U12(2,-6) U13(2.8,-6) U14(3.6,-6) U15(4.4,-6) U16(5.2,-6) U17(6,-6) U18(6.8,-6) V1(-6.8,-6.8) V2(-6,-6.8) V3(-5.2,-6.8) V4(-4.4,-6.8) V5(-3.6,-6.8) V6(-2.8,-6.8) V7(-2,-6.8) V8(-1.2,-6.8) V9(-0.4,-6.8) V10(0.4,-6.8) V11(1.2,-6.8) V12(2,-6.8) V13(2.8,-6.8) V14(3.6,-6.8) V15(4.4,-6.8) V16(5.2,-6.8) V17(6,-6.8) V18(6.8,-6.8)
BGA96_T9_P8_9X14
  round 0.356 smd: A1(-3.2,6.001) A2(-2.4,6.001) A3(-1.6,6.001) A7(1.6,6.001) A8(2.4,6.001) A9(3.2,6.001) B1(-3.2,5.201) B2(-2.4,5.201) B3(-1.6,5.201) B7(1.6,5.201) B8(2.4,5.201) B9(3.2,5.201) C1(-3.2,4.401) C2(-2.4,4.401) C3(-1.6,4.401) C7(1.6,4.401) C8(2.4,4.401) C9(3.2,4.401) D1(-3.2,3.6) D2(-2.4,3.6) D3(-1.6,3.6) D7(1.6,3.6) D8(2.4,3.6) D9(3.2,3.6) E1(-3.2,2.8) E2(-2.4,2.8) E3(-1.6,2.8) E7(1.6,2.8) E8(2.4,2.8) E9(3.2,2.8) F1(-3.2,2) F2(-2.4,2) F3(-1.6,2) F7(1.6,2) F8(2.4,2) F9(3.2,2) G1(-3.2,1.2) G2(-2.4,1.2) G3(-1.6,1.2) G7(1.6,1.2) G8(2.4,1.2) G9(3.2,1.2) H1(-3.2,0.4) H2(-2.4,0.4) H3(-1.6,0.4) H7(1.6,0.4) H8(2.4,0.4) H9(3.2,0.4) J1(-3.2,-0.4) J2(-2.4,-0.4) J3(-1.6,-0.4) J7(1.6,-0.4) J8(2.4,-0.4) J9(3.2,-0.4) K1(-3.2,-1.2) K2(-2.4,-1.2) K3(-1.6,-1.2) K7(1.6,-1.2) K8(2.4,-1.2) K9(3.2,-1.2) L1(-3.2,-2) L2(-2.4,-2) L3(-1.6,-2) L7(1.6,-2) L8(2.4,-2) L9(3.2,-2) M1(-3.2,-2.8) M2(-2.4,-2.8) M3(-1.6,-2.8) M7(1.6,-2.8) M8(2.4,-2.8) M9(3.2,-2.8) N1(-3.2,-3.6) N2(-2.4,-3.6) N3(-1.6,-3.6) N7(1.6,-3.6) N8(2.4,-3.6) N9(3.2,-3.6) P1(-3.2,-4.401) P2(-2.4,-4.401) P3(-1.6,-4.401) P7(1.6,-4.401) P8(2.4,-4.401) P9(3.2,-4.401) R1(-3.2,-5.201) R2(-2.4,-5.201) R3(-1.6,-5.201) R7(1.6,-5.201) R8(2.4,-5.201) R9(3.2,-5.201) T1(-3.2,-6.001) T2(-2.4,-6.001) T3(-1.6,-6.001) T7(1.6,-6.001) T8(2.4,-6.001) T9(3.2,-6.001)
BGA153_P14_P5_11P5X13
  round 0.254 smd: A1(-3.25,3.25) A2(-2.75,3.25) A3(-2.25,3.25) A4(-1.75,3.25) A5(-1.25,3.25) A6(-0.75,3.25) A7(-0.25,3.25) A8(0.25,3.25) A9(0.75,3.25) A10(1.25,3.25) A11(1.75,3.25) A12(2.25,3.25) A13(2.75,3.25) A14(3.25,3.25) B1(-3.25,2.75) B2(-2.75,2.75) B3(-2.25,2.75) B4(-1.75,2.75) B5(-1.25,2.75) B6(-0.75,2.75) B7(-0.25,2.75) B8(0.25,2.75) B9(0.75,2.75) B10(1.25,2.75) B11(1.75,2.75) B12(2.25,2.75) B13(2.75,2.75) B14(3.25,2.75) C1(-3.25,2.25) C2(-2.75,2.25) C3(-2.25,2.25) C4(-1.75,2.25) C5(-1.25,2.25) C6(-0.75,2.25) C7(-0.25,2.25) C8(0.25,2.25) C9(0.75,2.25) C10(1.25,2.25) C11(1.75,2.25) C12(2.25,2.25) C13(2.75,2.25) C14(3.25,2.25) D1(-3.25,1.75) D2(-2.75,1.75) D3(-2.25,1.75) D4(-1.75,1.75) D12(2.25,1.75) D13(2.75,1.75) D14(3.25,1.75) E1(-3.25,1.25) E2(-2.75,1.25) E3(-2.25,1.25) E5(-1.25,1.25) E6(-0.75,1.25) E7(-0.25,1.25) E8(0.25,1.25) E9(0.75,1.25) E10(1.25,1.25) E12(2.25,1.25) E13(2.75,1.25) E14(3.25,1.25) F1(-3.25,0.75) F2(-2.75,0.75) F3(-2.25,0.75) F5(-1.25,0.75) F10(1.25,0.75) F12(2.25,0.75) F13(2.75,0.75) F14(3.25,0.75) G1(-3.25,0.25) G2(-2.75,0.25) G3(-2.25,0.25) G5(-1.25,0.25) G10(1.25,0.25) G12(2.25,0.25) G13(2.75,0.25) G14(3.25,0.25) H1(-3.25,-0.25) H2(-2.75,-0.25) H3(-2.25,-0.25) H5(-1.25,-0.25) H10(1.25,-0.25) H12(2.25,-0.25) H13(2.75,-0.25) H14(3.25,-0.25) J1(-3.25,-0.75) J2(-2.75,-0.75) J3(-2.25,-0.75) J5(-1.25,-0.75) J10(1.25,-0.75) J12(2.25,-0.75) J13(2.75,-0.75) J14(3.25,-0.75) K1(-3.25,-1.25) K2(-2.75,-1.25) K3(-2.25,-1.25) K5(-1.25,-1.25) K6(-0.75,-1.25) K7(-0.25,-1.25) K8(0.25,-1.25) K9(0.75,-1.25) K10(1.25,-1.25) K12(2.25,-1.25) K13(2.75,-1.25) K14(3.25,-1.25) L1(-3.25,-1.75) L2(-2.75,-1.75) L3(-2.25,-1.75) L12(2.25,-1.75) L13(2.75,-1.75) L14(3.25,-1.75) M1(-3.25,-2.25) M2(-2.75,-2.25) M3(-2.25,-2.25) M4(-1.75,-2.25) M5(-1.25,-2.25) M6(-0.75,-2.25) M7(-0.25,-2.25) M8(0.25,-2.25) M9(0.75,-2.25) M10(1.25,-2.25) M11(1.75,-2.25) M12(2.25,-2.25) M13(2.75,-2.25) M14(3.25,-2.25) N1(-3.25,-2.75) N2(-2.75,-2.75) N3(-2.25,-2.75) N4(-1.75,-2.75) N5(-1.25,-2.75) N6(-0.75,-2.75) N7(-0.25,-2.75) N8(0.25,-2.75) N9(0.75,-2.75) N10(1.25,-2.75) N11(1.75,-2.75) N12(2.25,-2.75) N13(2.75,-2.75) N14(3.25,-2.75) P1(-3.25,-3.25) P2(-2.75,-3.25) P3(-2.25,-3.25) P4(-1.75,-3.25) P5(-1.25,-3.25) P6(-0.75,-3.25) P7(-0.25,-3.25) P8(0.25,-3.25) P9(0.75,-3.25) P10(1.25,-3.25) P11(1.75,-3.25) P12(2.25,-3.25) P13(2.75,-3.25) P14(3.25,-3.25)
DCK5_2P15X1P4
  rect 0.4x0.9 smd: 1(-0.65,-1.1) 2(0,-1.1) 3(0.65,-1.1) 4(0.65,1.1) 5(-0.65,1.1)
DGN-16X60
  oval 0.406x1.524 smd: 1(-0.975,-2.311) 2(-0.325,-2.311) 3(0.325,-2.311) 4(0.975,-2.311) 5(0.975,2.311) 6(0.325,2.311) 7(-0.325,2.311) 8(-0.975,2.311)
  rect 2.032x2.032 smd: 9(0,0)
HEADER10X2_SMD
  rect 0.711x2.794 smd: 1(-5.715,-2.705) 2(-5.715,2.705) 3(-4.445,-2.705) 4(-4.445,2.705) 5(-3.175,-2.705) 6(-3.175,2.705) 7(-1.905,-2.705) 8(-1.905,2.705) 9(-0.635,-2.705) 10(-0.635,2.705) 11(0.635,-2.705) 12(0.635,2.705) 13(1.905,-2.705) 14(1.905,2.705) 15(3.175,-2.705) 16(3.175,2.705) 17(4.445,-2.705) 18(4.445,2.705) 19(5.715,-2.705) 20(5.715,2.705)
HEADER23X2
  rect 1.524x1.524 hole 0.762: 1(0,0)
  round 1.524 hole 0.762: 2(0,2.54) 3(2.54,0) 4(2.54,2.54) 5(5.08,0) 6(5.08,2.54) 7(7.62,0) 8(7.62,2.54) 9(10.16,0) 10(10.16,2.54) 11(12.7,0) 12(12.7,2.54) 13(15.24,0) 14(15.24,2.54) 15(17.78,0) 16(17.78,2.54) 17(20.32,0) 18(20.32,2.54) 19(22.86,0) 20(22.86,2.54) 21(25.4,0) 22(25.4,2.54) 23(27.94,0) 24(27.94,2.54) 25(30.48,0) 26(30.48,2.54) 27(33.02,0) 28(33.02,2.54) 29(35.56,0) 30(35.56,2.54) 31(38.1,0) 32(38.1,2.54) 33(40.64,0) 34(40.64,2.54) 35(43.18,0) 36(43.18,2.54) 37(45.72,0) 38(45.72,2.54) 39(48.26,0) 40(48.26,2.54) 41(50.8,0) 42(50.8,2.54) 43(53.34,0) 44(53.34,2.54) 45(55.88,0) 46(55.88,2.54)
LED_0603
  rect 0.762x1.016 smd: 1(-0.826,0) 2(0.826,0)
MTGH200C125D_PL
  round 4.445 hole 3.175: 1(0,0)
OSC4_61X65LS_79X98SMD
  rect 0.711x0.889 smd: 1(-0.826,-0.775) 2(0.826,-0.775) 3(0.826,0.775) 4(-0.826,0.775)
QFN32_5X5MM_EP3P3MM
  oval 0.254x0.838 smd: 1(-1.751,-2.515) 8(1.751,-2.515) 17(1.751,2.515) 24(-1.751,2.515)
  rect 0.254x0.838 smd: 2(-1.251,-2.515) 3(-0.751,-2.515) 4(-0.25,-2.515) 5(0.25,-2.515) 6(0.751,-2.515) 7(1.251,-2.515) 18(1.251,2.515) 19(0.751,2.515) 20(0.25,2.515) 21(-0.25,2.515) 22(-0.751,2.515) 23(-1.251,2.515)
  oval 0.838x0.254 smd: 9(2.515,-1.751) 16(2.515,1.751) 25(-2.515,1.751) 32(-2.515,-1.751)
  rect 0.838x0.254 smd: 10(2.515,-1.251) 11(2.515,-0.751) 12(2.515,-0.25) 13(2.515,0.25) 14(2.515,0.751) 15(2.515,1.251) 26(-2.515,1.251) 27(-2.515,0.751) 28(-2.515,0.25) 29(-2.515,-0.25) 30(-2.515,-0.751) 31(-2.515,-1.251)
  rect 3.404x3.404 smd: 33(0,0)
RD205SMD_250D
  rect 3.048x1.651 smd: 1(-2.603,0) 2(2.603,0)
RJ45-7499010211A
  round 1.016 hole 3.251 unplated: (-1.27,-6.35) (10.16,-6.35)
  rect 1.524x1.524 hole 1.016: 1(0,0)
  round 1.524 hole 1.016: 2(1.27,2.54) 3(2.54,0) 4(3.81,2.54) 5(5.08,0) 6(6.35,2.54) 7(7.62,0) 8(8.89,2.54) 9(-1.88,-11.252) 10(0.66,-9.728) 11(8.23,-11.252) 12(10.77,-9.728)
  round 2.286 hole 1.6: 13(-3.429,-3.302) 14(12.319,-3.302)
SD-MICRO-SCHA5B0300
  rect 0.914x0.457 smd: 1(-7.257,0) 2(-7.257,-0.7) 3(-7.257,-1.4) 4(-7.257,-2.1) 5(7.257,-2.1) 6(7.257,-1.4) 7(7.257,-0.7) 8(7.257,0)
  rect 0.508x0.889 smd: 9(3.775,9.989) 10(-5.975,9.989)
  rect 0.889x2.007 smd: 11(-7.25,7.635) 12(7.25,6.335)
  rect 1.118x1.524 smd: 13(-7.196,-3.365) 14(7.196,-3.365)
  rect 1.194x1.092 smd: 15(-3.425,10.488) 16(2.575,10.488)
SIP6
  rect 1.524x1.524 hole 1.016: 1(0,0)
  round 1.524 hole 1.016: 2(0,-2.54) 3(0,-5.08) 4(0,-7.62) 5(0,-10.16) 6(0,-12.7)
SM-7351-IND-0805
  rect 1.397x1.549 smd: 1(-0.95,0) 2(0.95,0)
SM-7351-RES-0402
  round 0.635 smd: 1(-0.508,0) 2(0.508,0)
SMINI6-F3-B
  rect 0.305x0.95 smd: 1(0.65,0.75) 2(0,0.75) 3(-0.65,0.75) 4(-0.65,-0.75) 5(0,-0.75) 6(0.65,-0.75)
SO8-25X75
  oval 0.635x1.905 smd: 1(-1.905,-2.794) 2(-0.635,-2.794) 3(0.635,-2.794) 4(1.905,-2.794) 5(1.905,2.794) 6(0.635,2.794) 7(-0.635,2.794) 8(-1.905,2.794)
SOT23-5
  rect 0.635x1.016 smd: 1(-0.953,-1.295) 2(0,-1.295) 3(0.953,-1.295) 4(0.953,1.295) 5(-0.953,1.295)
SW_4P
  rect 1.422x0.813 smd: 1(-1.8,-0.94) 2(-1.8,0.94) 3(1.8,-0.94) 4(1.8,0.94)
TDFN8_P5_2P0
  rect 1.219x0.61 smd: (0,0)
  rect 0.305x0.711 smd: 1(-0.75,-0.85) 2(-0.25,-0.85) 3(0.25,-0.85) 4(0.75,-0.85) 5(0.75,0.85) 6(0.25,0.85) 7(-0.25,0.85) 8(-0.75,0.85)
TP1-8040
  round 1.524 hole 1.016: 1(0,0)
TP60C33D
  round 1.524 hole 0.762: 1(0,0)
TP60C_SMD
  round 1.27 smd: 1(0,0)
U_6_DRY
  rect 0.305x0.508 smd: 1(-0.5,-0.439) 2(0,-0.439) 3(0.5,-0.439) 4(0.5,0.439) 5(0,0.439) 6(-0.5,0.439)
U_8_DCU
  rect 0.254x1.27 smd: 1(-0.749,-1.473) 2(-0.249,-1.473) 3(0.249,-1.473) 4(0.749,-1.473) 5(0.749,1.473) 6(0.249,1.473) 7(-0.249,1.473) 8(-0.749,1.473)
U_48_RSL
  rect 0.8x0.2 smd: 1(-3.075,2.2) 2(-3.075,1.8) 3(-3.075,1.4) 4(-3.075,1) 5(-3.075,0.6) 6(-3.075,0.2) 7(-3.075,-0.2) 8(-3.075,-0.6) 9(-3.075,-1) 10(-3.075,-1.4) 11(-3.075,-1.8) 12(-3.075,-2.2) 25(3.075,-2.2) 26(3.075,-1.8) 27(3.075,-1.4) 28(3.075,-1) 29(3.075,-0.6) 30(3.075,-0.2) 31(3.075,0.2) 32(3.075,0.6) 33(3.075,1) 34(3.075,1.4) 35(3.075,1.8) 36(3.075,2.2)
  rect 0.2x0.8 smd: 13(-2.2,-3.075) 14(-1.8,-3.075) 15(-1.4,-3.075) 16(-1,-3.075) 17(-0.6,-3.075) 18(-0.2,-3.075) 19(0.2,-3.075) 20(0.6,-3.075) 21(1,-3.075) 22(1.4,-3.075) 23(1.8,-3.075) 24(2.2,-3.075) 37(2.2,3.075) 38(1.8,3.075) 39(1.4,3.075) 40(1,3.075) 41(0.6,3.075) 42(0.2,3.075) 43(-0.2,3.075) 44(-0.6,3.075) 45(-1,3.075) 46(-1.4,3.075) 47(-1.8,3.075) 48(-2.2,3.075)
  rect 4.05x4.05 smd: 49(-0.225,0.225)
unnamed#2
  round 2.032 hole 2.032 unplated: (0,0)
unnamed#3
  round 1.016 smd: 1(0,0)
USB-003A-4P-90D
  rect 1.321x1.321 hole 0.914: 1(-3.5,2.71)
  round 1.321 hole 0.914: 2(-1,2.71) 3(1,2.71) 4(3.5,2.71)
  round 2.946 hole 2.337: 5(-6.57,0) 6(6.57,0)
XTAL4_126-216SMD
  rect 1.27x1.905 smd: 1(-2.748,-1.6) 2(2.751,-1.6) 3(2.751,1.6) 4(-2.748,1.6)
XTAL150SMD_125X196
  rect 1.778x2.159 smd: 1(-1.9,0) 2(1.9,0)

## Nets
DGND: C1.1 C2.1 C3.1 C4.1 C7.1 C8.1 C9.1 C10.1 C11.1 C12.1 C13.1 C14.1 C15.1 C16.2 C17.2 C18.2 C19.2 C20.2 C24.2 C28.2 C29.2 C30.2 C34.2 C35.2 C36.2 C37.2 C38.2 C39.1 C40.1 C41.2 C42.2 C43.2 C44.2 C45.2 C46.2 C47.2 C48.2 C49.2 C50.2 C51.2 C52.2 C53.2 C54.2 C55.1 C56.1 C57.1 C58.2 C59.2 C60.1 C61.1 C62.1 C63.2 C64.2 C65.2 C66.2 C67.2 C68.1 C69.1 C70.1 C71.1 C72.1 C73.1 C74.1 C75.1 C76.1 C77.2 C78.2 C79.2 C80.2 C81.2 C82.2 C83.2 C84.2 C85.2 C86.2 C87.2 C88.2 C89.2 C90.2 C91.2 C92.2 C94.2 C95.1 C96.1 C97.2 C98.2 C99.2 C100.2 C101.2 C102.2 C103.2 C104.2 C105.2 C106.2 C107.2 C108.2 C109.2 C110.2 C111.2 C112.2 C113.2 C114.2 C115.2 C116.2 C117.2 C118.1 C119.2 C120.2 C121.2 C122.1 C123.2 C124.2 C125.2 C126.1 C127.2 C128.2 C129.2 C130.2 C131.2 C132.2 C133.1 C134.2 C135.2 C136.2 C137.2 C138.2 C139.2 C140.2 C141.2 C142.2 C143.2 C152.2 C153.2 C154.2 C155.1 C158.2 C159.2 C161.2 C162.1 FB3.2 J1.1 J4.4 J5.4 P2.4(TDIS) P2.8(GND1) P2.10(GND2) P2.12(GND3) P2.16(GND4) P2.20(GND5) P3.4(P4) P4.5(G1) P5.8(GND) P8.1 P8.2(26) P9.1 P9.2(26) P9.43(22) P9.44(47) P9.45(23) P9.46(48) P10.6(VSS) P10.9(GND) Q1.1(4) Q1.4 Q2.1(4) Q2.4 R10.2 R12.1 R22.1 R25.2 R29.1 R30.1 R49.1 R53.2 R54.1 R76.2 R77.2 R78.2 R79.2 R80.2 R81.2 R82.2 R83.2 R84.2 R85.2 R86.2 R87.2 R88.2 R89.2 R90.2 R91.2 R92.2 R93.2 R94.2 R95.2 R96.1 R99.1 R100.2 R115.2 R116.2 R117.2 R118.2 R130.1 R132.1 R135.2 R136.1 R144.2 R145.2 R164.2 R165.2 R170.2 S1.1(A1) S1.3(A2) S2.2(B1) S2.4(B2) S3.1(A1) S3.3(A2) TP1.1(TP) TP8.1(TP) U2.30(PGND) U2.41(AGND) U2.49(PPAD) U3.3(GND) U4.5(GND1) U4.6(GND3) U4.7(GND2) U4.8(GND4) U5.A1(VSS1) U5.A18(VSS2) U5.F8(VSS3) U5.G8(VSS4) U5.G9(VSS5) U5.G11(VSS6) U5.G12(VSS7) U5.H6(VSS8) U5.H7(VSS9) U5.H8(VSS10) U5.H9(VSS11) U5.H10(VSS12) U5.H12(VSS13) U5.J6(VSS14) U5.J7(VSS15) U5.J8(VSS16) U5.J9(VSS17) U5.J10(VSS18) U5.J11(VSS19) U5.K7(VSS20) U5.K9(VSS21) U5.K10(VSS22) U5.K11(VSS23) U5.L10(VSS24) U5.L11(VSS25) U5.L12(VSS26) U5.L13(VSS27) U5.M6(VSS28) U5.M7(VSS29) U5.M8(VSS30) U5.M9(VSS31) U5.M10(VSS32) U5.M12(VSS33) U5.M14(VSSA_USB2) U5.N7(VSS34) U5.N10(VSS35) U5.N11(VSS36) U5.N14(VSSA_USB1) U5.V1(VSS37) U5.V18(VSS38) U7.2(VSS) U8.1(GND) U8.9(PAD) U9.4(GND) U10.4(GND) U12.A9(VSS1) U12.B1(VSSQ1) U12.B3(VSS2) U12.B9(VSSQ2) U12.D1(VSSQ3) U12.D8(VSSQ4) U12.E1(VSS3) U12.E2(VSSQ5) U12.E8(VSSQ6) U12.F9(VSSQ7) U12.G1(VSSQ8) U12.G8(VSS4) U12.G9(VSSQ9) U12.J2(VSS5) U12.J8(VSS6) U12.M1(VSS7) U12.M9(VSS8) U12.P1(VSS9) U12.P9(VSS10) U12.T1(VSS11) U12.T9(VSS12) U13.C4(VSSQ4) U13.E7(VSS2) U13.G5(VSS1) U13.H10(VSS3) U13.K8(VSS4) U13.N2(VSSQ1) U13.N5(VSS5) U13.P4(VSSQ3) U13.P6(VSSQ2) U14.33(GND_EP) U15.1(1\O\E\) U15.4(GND) U16.3(GND) Y4.2(GND)
GND_EARTH: C163.2 C164.2 C165.2 C166.2 MTG1.1(TP) MTG2.1(TP) MTG3.1(TP) MTG4.1(TP) P3.5(SHELD1) P3.6(PAD4) P4.6(G3) P4.7(G2) P4.8(G5) P4.9(G4) P5.13(SHD1) P5.14(SHD2) P10.11(GND3) P10.12(GND4) P10.13(GND5) P10.14(GND6) P10.15(GND7) P10.16(GND8) R136.2
GND_OSC0: C25.2 C26.2 R29.2 R173.2 R174.2 U5.V11(VSS_OSC0) U17.4(GND)
GND_OSC1: C21.1 C22.1 R30.2 U5.A5(VSS_RTC)
GNDA_ADC: C31.2 C32.2 C33.2 C93.2 FB3.1 P9.34(42) U5.A9(VREFN) U5.E8(VSSA_ADC)
VBUS: FB7.2 P3.1(P1)
VDD_1V8: C14.2 C78.1 C86.1 C88.1 FB1.1 FB2.2 R9.2 U2.40(LDO3) U5.D10(VDDS_SRAM_MPU_BB) U5.E9(VDDS_SRAM_CORE_BG) U5.N16(VDDA1P8V_USB0) U5.R16(VDDA1P8V_USB1)
VDD_3V3A: C15.2 C37.1 C38.1 C56.2 C57.2 C58.1 C59.1 C60.2 C61.2 C66.1 C67.1 C68.2 C69.2 C70.2 C71.2 C72.2 C73.2 C74.2 C75.2 C76.2 C77.1 C87.1 C152.1 C158.1 C159.1 R1.1 R3.1 R4.1 R14.1 R52.1 R55.1 R56.1 R57.1 R58.1 R59.1 R60.1 R61.1 R62.1 R63.1 R64.1 R65.1 R66.1 R67.1 R68.1 R69.1 R70.1 R156.1 R169.2 R171.1 R172.1 R175.1 U2.43(LDO4) U3.5(VCC) U4.1(EN) U5.E10(VDDSHV61) U5.E11(VDDSHV62) U5.E12(VDDSHV63) U5.E13(VDDSHV64) U5.F14(VDDSHV65) U5.G14(VDDSHV66) U5.H14(VDDSHV41) U5.J14(VDDSHV42) U5.K14(VDDSHV51) U5.L14(VDDSHV52) U5.N5(VDDSHV67) U5.N15(VDDA3P3V_USB0) U5.P5(VDDSHV68) U5.P6(VDDSHV69) U5.P7(VDDSHV11) U5.P8(VDDSHV12) U5.P10(VDDSHV21) U5.P11(VDDSHV22) U5.P12(VDDSHV31) U5.P13(VDDSHV32) U5.R15(VDDA3P3V_USB1) U7.4(VCC) U17.8(VDD) Y4.4(VCC)
VDD_3V3AUX: C18.1 D1.2(A) U2.1(VLDO2)
VDD_3V3B: C20.1 C29.1 C126.2 C127.1 C128.1 C129.1 C130.1 C135.1 C153.1 C154.1 C155.2 FB4.1 J4.3 J5.3 P2.5(TVDD) P9.3(2) P9.4(27) P10.4(VDD) R11.1 R23.1 R24.1 R101.1 R102.1 R103.1 R104.1 R105.1 R106.1 R107.1 R108.1 R109.1 R110.1 R111.1 R112.2 R113.2 R114.2 R119.1 R150.1 R151.1 R152.1 R153.1 R154.1 R155.1 R157.2 R163.1 U4.3(OUT) U13.C6(VCCQ4) U13.E6(VCC3) U13.F5(VCC2) U13.J10(VCC0) U13.K9(VCC1) U13.M4(VCCQ5) U13.N4(VCCQ3) U13.P3(VCCQ1) U13.P5(VCCQ2) U14.12(VDDIO) U15.7(2OE) U15.8(VCC)
VDD_5V: C2.2 P9.5(3) P9.6(28) R168.2 U2.10(AC)
VDD_ADC: C93.1 FB2.1 P9.32(41) R27.1 U5.D8(VDDA_ADC)
VDD_CORE: C11.2 C39.2 C40.2 C41.1 C42.1 C43.1 C44.1 C45.1 C46.1 C47.1 C48.1 C49.1 C50.1 C51.1 C52.1 C53.1 C54.1 C55.2 L3.2 U2.29(VDCDC3) U5.F6(VDD_CORE1) U5.F7(VDD_CORE2) U5.G6(VDD_CORE3) U5.G7(VDD_CORE4) U5.G10(VDD_CORE5) U5.H11(VDD_CORE6) U5.J12(VDD_CORE7) U5.K6(VDD_CORE8) U5.K8(VDD_CORE9) U5.K12(VDD_CORE10) U5.L6(VDD_CORE11) U5.L7(VDD_CORE12) U5.L8(VDD_CORE13) U5.L9(VDD_CORE14) U5.M11(VDD_CORE15) U5.M13(VDD_CORE16) U5.N8(VDD_CORE17) U5.N9(VDD_CORE18) U5.N12(VDD_CORE19) U5.N13(VDD_CORE20)
VDD_MPU: C12.2 C62.2 C63.1 C64.1 C65.1 L2.2 U2.24(VDCDC2) U5.F10(VDD_MPU1) U5.F11(VDD_MPU2) U5.F12(VDD_MPU3) U5.F13(VDD_MPU4) U5.G13(VDD_MPU5) U5.H13(VDD_MPU6) U5.J13(VDD_MPU7)
VDD_MPUON: TP2.1(TP) U5.A2(VDD_MPU_MON)
VDD_PHYA: C131.1 C132.1 C133.2 FB4.2 R120.2 R121.2 R122.2 R123.2 R137.2 U14.1(VDD2A) U14.27(VDD1A)
VDD_PLL: C79.1 C92.1 C94.1 C106.1 FB1.2 U5.E7(VDDS_PLL_DDR) U5.H15(VDDS_PLL_MPU) U5.R10(VDDS_PLL_CORE_LCD) U5.R11(VDDS_OSC)
VDD_RTC: C104.1 U5.D6(CAP_VDD_RTC)
VDDS: C80.1 C81.1 C82.1 C83.1 C84.1 C85.1 R8.2 R9.1 U5.E6(VDDS1) U5.E14(VDDS2) U5.F9(VDDS3) U5.K13(VDDS4) U5.N6(VDDS5) U5.P9(VDDS6) U5.P14(VDDS7)
VDDS_DDR: C9.2 C95.2 C96.2 C97.1 C98.1 C99.1 C100.1 C101.1 C102.1 C103.1 C107.1 C108.1 C109.1 C110.1 C111.1 C112.1 C113.1 C114.1 C115.1 C116.1 C117.1 C118.2 C119.1 C120.1 C121.1 C122.2 R6.2 R97.1 R98.1 U5.E5(VDDS_DDR1) U5.F5(VDDS_DDR2) U5.G5(VDDS_DDR3) U5.H5(VDDS_DDR4) U5.J5(VDDS_DDR5) U5.K5(VDDS_DDR6) U5.L5(VDDS_DDR7) U12.A1(VDDQ1) U12.A8(VDDQ2) U12.B2(VDD1) U12.C1(VDDQ3) U12.C9(VDDQ4) U12.D2(VDDQ5) U12.D9(VDD9) U12.E9(VDDQ7) U12.F1(VDDQ8) U12.G7(VDD2) U12.H2(VDDQ9) U12.H9(VDDQ10) U12.K2(VDD4) U12.K8(VDD5) U12.N1(VDD6) U12.N9(VDD7) U12.R1(VDD8) U12.R9(VDD3)
AIN0: P9.39(20) U5.B6(AIN0)
AIN1: P9.40(45) U5.C7(AIN1)
AIN2: P9.37(19) U5.B7(AIN2)
AIN3: P9.38(44) U5.A7(AIN3)
AIN4: P9.33(17) U5.C8(AIN4)
AIN5: P9.36(43) U5.B8(AIN5)
AIN6: P9.35(18) U5.A8(AIN6)
AIN7: R163.2 R164.1 U5.C9(AIN7)
B_UART0_RX: J1.4 R165.1 U15.2(1A)
B_UART0_TX: J1.5 U15.3(2Y)
CAP_VBB_MPU: C91.1 U5.C10(CAP_VBB_MPU)
CAP_VDD_SRAM_CORE: C89.1 U5.D9(CAP_VDD_SRAM_CORE)
CAP_VDD_SRAM_MPU: C90.1 U5.D11(CAP_VDD_SRAM_MPU)
CLKOUT2: P2.18(EMU3) P9.41(21) R19.2 R20.1
CLKOUT_SRC: R19.1 U5.D14(EVENT_INTR1/TCLKIN/CLKOUT2/TIME)
CRS: R139.2 U14.14(CRS)
DDR_A0: U5.F3(DDR_A0) U12.N3(A0)
DDR_A1: U5.H1(DDR_A1) U12.P7(A1)
DDR_A2: U5.E4(DDR_A2) U12.P3(A2)
DDR_A3: U5.C3(DDR_A3) U12.N2(A3)
DDR_A4: U5.C2(DDR_A4) U12.P8(A4)
DDR_A5: U5.B1(DDR_A5) U12.P2(A5)
DDR_A6: U5.D5(DDR_A6) U12.R8(A6)
DDR_A7: U5.E2(DDR_A7) U12.R2(A7)
DDR_A8: U5.D4(DDR_A8) U12.T8(A8)
DDR_A9: U5.C1(DDR_A9) U12.R3(A9)
DDR_A10: U5.F4(DDR_A10) U12.L7(A10)
DDR_A11: U5.F2(DDR_A11) U12.R7(A11)
DDR_A12: U5.E3(DDR_A12) U12.N7(A12)
DDR_A13: U5.H3(DDR_A13) U12.T3(A13)
DDR_A14: U5.H4(DDR_A14) U12.T7(A14)
DDR_A15: U5.D3(DDR_A15) U12.M7(A15)
DDR_BA0: U5.C4(DDR_BA0) U12.M2(BA0)
DDR_BA1: U5.E1(DDR_BA1) U12.N8(BA1)
DDR_BA2: U5.B3(DDR_BA2) U12.M3(BA2)
DDR_CASN: U5.F1(DDR_CASN) U12.K3(CASN)
DDR_CKE: R96.2 U5.G3(DDR_CKE) U12.K9(CKE)
DDR_CLK: U5.D2(DDR_CK) U12.J7(CK)
DDR_CLKN: U5.D1(DDR_NCK) U12.K7(CKN)
DDR_CSN: U5.H2(DDR_CSN0) U12.L2(CSN)
DDR_D0: U5.M3(DDR_D0) U12.E3(DQ0)
DDR_D1: U5.M4(DDR_D1) U12.F7(DQ1)
DDR_D2: U5.N1(DDR_D2) U12.F2(DQ2)
DDR_D3: U5.N2(DDR_D3) U12.F8(DQ3)
DDR_D4: U5.N3(DDR_D4) U12.H3(DQ4)
DDR_D5: U5.N4(DDR_D5) U12.H8(DQ5)
DDR_D6: U5.P3(DDR_D6) U12.G2(DQ6)
DDR_D7: U5.P4(DDR_D7) U12.H7(DQ7)
DDR_D8: U5.J1(DDR_D8) U12.D7(DQ8)
DDR_D9: U5.K1(DDR_D9) U12.C3(DQ9)
DDR_D10: U5.K2(DDR_D10) U12.C8(DQ10)
DDR_D11: U5.K3(DDR_D11) U12.C2(DQ11)
DDR_D12: U5.K4(DDR_D12) U12.A7(DQ12)
DDR_D13: U5.L3(DDR_D13) U12.A2(DQ13)
DDR_D14: U5.L4(DDR_D14) U12.B8(DQ14)
DDR_D15: U5.M1(DDR_D15) U12.A3(DQ15)
DDR_DQM0: U5.M2(DDR_DQM0) U12.E7(LDM)
DDR_DQM1: U5.J2(DDR_DQM1) U12.D3(UDM)
DDR_DQS0: U5.P1(DDR_DQS0) U12.F3(LDQS)
DDR_DQS1: U5.L1(DDR_DQS1) U12.C7(UDQS)
DDR_DQSN0: U5.P2(DDR_DQSN0) U12.G3(LDQSN)
DDR_DQSN1: U5.L2(DDR_DQSN1) U12.B7(UDQSN)
DDR_ODT: U5.G1(DDR_ODT) U12.K1(ODT)
DDR_RASN: U5.G4(DDR_RASN) U12.J3(RASN)
DDR_RESETN: R97.2 U5.G2(DDR_RESETN) U12.T2(RESET#)
DDR_VREF: C28.1 C123.1 C124.1 R98.2 R100.1 U5.J4(VREFSSTL) U12.H1(VREF_DQ) U12.M8(VREF_CA)
DDR_VTP: R22.2 U5.J3(DDR_VTP)
DDR_WEN: U5.B2(DDR_WEN) U12.L3(WEN)
EHRPWM1A: P9.14(32) U5.U14(GPMC_A2/GMII2_TXD3/RGMII2_TD3/M)
EHRPWM1B: P9.16(33) U5.T14(GPMC_A3/GMII2_TXD2/RGMII2_TD2/M)
EHRPWM2A: P8.19(10) U5.U10(GPMC_AD8/LCD_DATA23/MMC1_DAT0/M)
EHRPWM2B: P8.13(7) U5.T10(GPMC_AD9/LCD_DATA22/MMC1_DAT1/M)
EMMC_RSTN: R111.2 R162.2 U13.K5(R\S\T\)
EMMC_VCCI: C125.1 U13.C2(VCCI)
ENZ_KALDO_1P8V: R54.2 U5.B4(ENZ_KALDO_1P8V)
ETH_TXD4: R145.1 U14.18(NINT/TXER/TXD4)
GPIO0_7: P9.42(46) R50.1 R51.1
GPIO0_7SRC: R50.2 U5.C18(ECAP0_IN_PWM0_OUT/UART3_TXD/SPI)
GPIO0_26: P8.14(32) U5.T11(GPMC_AD10/LCD_DATA21/MMC1_DAT2/)
GPIO0_27: P8.17(9) U5.U12(GPMC_AD11/LCD_DATA20/MMC1_DAT3/)
GPIO1_12: P8.12(31) U5.T12(GPMC_AD12/LCD_DATA19/MMC1_DAT4/)
GPIO1_13: P8.11(6) U5.R12(GPMC_AD13/LCD_DATA18/MMC1_DAT5/)
GPIO1_14: P8.16(33) U5.V13(GPMC_AD14/LCD_DATA17/MMC1_DAT6/)
GPIO1_15: P8.15(8) U5.U13(GPMC_AD15/LCD_DATA16/MMC1_DAT7/)
GPIO1_16: P9.15(8) R160.2 R161.2
GPIO1_17: P9.23(12) U5.V14(GPMC_A1/GMII2_RXDV/RGMII2_RCTL/)
GPIO1_28: P9.12(31) U5.U18(GPMC_BE1N/GMII2_COL/GPMC_CSN6/M)
GPIO1_29: P8.26(38) U5.V6(GPMC_CSN0/GPIO1_29)
GPIO2_1: P8.18(34) U5.V12(GPMC_CLK/LCD_MEM_CLK/GPMC_WAIT1)
GPIO3_18: R51.2 U5.B12(MCASP0_ACLKR/EQEP0A_IN/MCASP0_A)
GPIO3_19: P9.27(14) U5.C13(MCASP0_FSR/EQEP0B_IN/MCASP0_AXR)
GPIO3_20: R20.2 U5.D13(MCASP0_AXR1/EQEP0_INDEX//MCASP1)
GPIO3_21: P9.25(13) R167.2 U5.A14(MCASP0_AHCLKX/EQEP0_STROBE/MCAS)
GRN_C: P5.10(GRNC) R132.2
GRNA: C163.1 C165.1 P5.9(GRNA) U14.3(LED1/REGOFF)
HDMI_INT: R169.1 R170.1 U5.U16(GPMC_A9/GMII2_RXD2/RGMII2_RD2/M)
HDMICLK_DISN: U5.V17(GPMC_A11/GMII2_RXD0/RGMII2_RD0/) Y4.1(OE)
I2C0_SCL: R3.2 U2.28(SCL) U5.C16(I2C0_SCL/TIMER7/UART2_RTSN/ECAP) U7.1(SCL)
I2C0_SDA: R4.2 U2.27(SDA) U5.C17(I2C0_SDA/TIMER4/UART2_CTSN/ECAP) U7.3(SDA)
I2C1_SCL: P9.17(9) U5.A16(SPI0_CS0/MMC2_SDWP/I2C1_SCL/EHR)
I2C1_SDA: P9.18(34) U5.B16(SPI0_D1/MMC1_SDWP/I2C1_SDA/EHRP)
I2C2_SCL: J4.1 P9.19(10) U5.D17(UART1_RTSN/TIMER5/DCAN0_RX/I2C2)
I2C2_SDA: J4.2 P9.20(35) U5.D18(UART1_CTSN/TIMER6/DCAN0_TX/I2C2)
JTAG_EMU0: P2.13(EMU0) R23.2 U5.C14(EMU0/GPIO3_7)
JTAG_EMU1: P2.14(EMU1) R24.2 U5.B14(EMU1/GPIO3_8)
JTAG_TCK: P2.9(TCKRTN) P2.11(TCK) U5.A12(TCK)
JTAG_TDI: P2.3(TDI) U5.B11(TDI)
JTAG_TDO: P2.7(TDO) U5.A11(TDO)
JTAG_TMS: P2.1(TMS) U5.C11(TMS)
JTAG_TRSTN: P2.2(TRSTN) R25.1 U5.B10(NTRST)
LCD_DATA0: P8.45(23) R70.2 R95.1 U5.R1(LCD_DATA0/GPMC_A0//EHRPWM2A//PR)
LCD_DATA1: P8.46(48) R69.2 R94.1 U5.R2(LCD_DATA1/GPMC_A1//EHRPWM2B//PR)
LCD_DATA2: P8.43(22) R68.2 R75.1 R93.1 U5.R3(LCD_DATA2/GPMC_A2//EHRPWM2_TRIP)
LCD_DATA3: P8.44(47) R67.2 R92.1 U5.R4(LCD_DATA3/GPMC_A3//EHRPWM2_SYNC)
LCD_DATA4: P8.41(21) R66.2 R91.1 U5.T1(LCD_DATA4/GPMC_A4//EQEP2A_IN//P)
LCD_DATA5: P8.42(46) R65.2 R90.1 U5.T2(LCD_DATA5/GPMC_A5//EQEP2B_IN//P)
LCD_DATA6: P8.39(20) R64.2 R89.1 U5.T3(LCD_DATA6/GPMC_A6/PR1_EDIO_DATA)
LCD_DATA7: P8.40(45) R63.2 R88.1 U5.T4(LCD_DATA7/GPMC_A7/PR1_EDIO_DATA)
LCD_DATA8: P8.37(19) R62.2 R87.1 U5.U1(LCD_DATA8/GPMC_A12/EHRPWM1_TRIP)
LCD_DATA9: P8.38(44) R61.2 R86.1 U5.U2(LCD_DATA9/GPMC_A13/EHRPWM1_SYNC)
LCD_DATA10: P8.36(43) R60.2 R85.1 U5.U3(LCD_DATA10/GPMC_A14/EHRPWM1A/MC)
LCD_DATA11: P8.34(42) R59.2 R84.1 U5.U4(LCD_DATA11/GPMC_A15/EHRPWM1B/MC)
LCD_DATA12: P8.35(18) R58.2 R83.1 U5.V2(LCD_DATA12/GPMC_A16/EQEP1A_IN/M)
LCD_DATA13: P8.33(17) R57.2 R82.1 U5.V3(LCD_DATA13/GPMC_A17/EQEP1B_IN/M)
LCD_DATA14: P8.31(16) R56.2 R81.1 U5.V4(LCD_DATA14/GPMC_A18/EQEP1_INDEX)
LCD_DATA15: P8.32(41) R55.2 R80.1 U5.T5(LCD_DATA15/GPMC_A19/EQEP1_STROB)
LCD_DE: P8.30(40) R48.2
LCD_HSYNC: P8.29(15) R47.2
LCD_PCLK: P8.28(39) R45.2
LCD_VSYNC: P8.27(14) R46.2
LCDDE: R48.1 U5.R6(LCD_AC_BIAS_EN/GPMC_A11//PR1_ED)
LCDPCLK: R45.1 U5.V5(LCD_PCLK/GPMC_A10//PR1_EDIO_DAT)
LCDVHYNC: R47.1 U5.R5(LCD_HSYNC/GPMC_A9//PR1_EDIO_DAT)
LCDVSYNC: R46.1 U5.U5(LCD_VSYNC/GPMC_A8//PR1_EDIO_DAT)
LDO_PGOOD: U2.46(LDO_PGOOD) U5.B5(RTC_PORZN)
LEDAA: D2.2(A) R72.2
LEDAC: D2.1(C) Q1.6(3)
LEDBA: D3.2(A) R73.2
LEDBC: D3.1(C) Q1.3
LEDCA: D4.2(A) R74.2
LEDCC: D4.1(C) Q2.6(3)
LEDDA: D5.2(A) R71.2
LEDDC: D5.1(C) Q2.3
MDIO_CLK: U5.M18(MDIO_CLK/TIMER5/UART5_TXD/UART3) U14.17(MDC)
MDIO_DATA: R119.2 U5.M17(MDIO_DATA/TIMER6/UART5_RXD/UART) U14.16(MDIO)
MII1_COL: R138.1 U5.H16(GMII1_COL/RMII2_REFCLK/SPI1_SCL)
MII1_CRS_DV: R139.1 U5.H17(GMII1_CRS/RMII1_CRS_DV/SPI1_D0/)
MII1_REFCLK: R28.2 R124.1 R140.1
MII1_RXCLK: R131.1 U5.L18(GMII1_RXCLK/UART2_TXD/RGMII1_RC)
MII1_RXD0: R128.1 U5.M16(GMII1_RXD0/RMII1_RXD0/RGMII1_RD)
MII1_RXD1: R127.1 U5.L15(GMII1_RXD1/RMII1_RXD1/RGMII1_RD)
MII1_RXD2: R126.1 U5.L16(GMII1_RXD2/UART3_TXD/RGMII1_RD2)
MII1_RXD3: R125.1 U5.L17(GMII1_RXD3/UART3_RXD/RGMII1_RD3)
MII1_RXDV: R129.1 U5.J17(GMII1_RXDV/LCD_MEMORY_CLK/RGMII)
MII1_RXERR: R133.1 U5.J15(GMII1_RXERR/RMII1_RXERR/SPI1_D1)
MII1_TXCLK: R134.1 U5.K18(GMII1_TXCLK/UART2_RXD/RGMII1_TC)
MII1_TXD0: U5.K17(GMII1_TXD0/RMII1_TXD0/RGMII1_TD) U14.22(TXD0)
MII1_TXD1: U5.K16(GMII1_TXD1/RMII1_TXD1/RGMII1_TD) U14.23(TXD1)
MII1_TXD2: U5.K15(GMII1_TXD2/DCAN0_RX/RGMII1_TD2/) U14.24(TXD2)
MII1_TXD3: U5.J18(GMII1_TXD3/DCAN0_TX/RGMII1_TD3/) U14.25(TXD3)
MII1_TXEN: U5.J16(GMII1_TXEN/RMII1_TXEN/RGMII1_TC) U14.21(TXEN)
MMC0_CD: P2.19(EMU4) P10.10(CD) R157.1 U5.C15(SPI0_CS1/UART3_RXD/ECAP1_IN_PWM)
MMC0_CLKO: P10.5(CLOCK) R152.2 U5.G17(MMC0_CLK/GPMC_A24/UART3_CTSN/UA)
MMC0_CMD: P10.3(CMD) R151.2 U5.G18(MMC0_CMD/GPMC_A25/UART3_RTSN/UA)
MMC0_DAT0: P10.7(DAT0) R153.2 U5.G16(MMC0_DAT0/GPMC_A23/UART5_RTSN/U)
